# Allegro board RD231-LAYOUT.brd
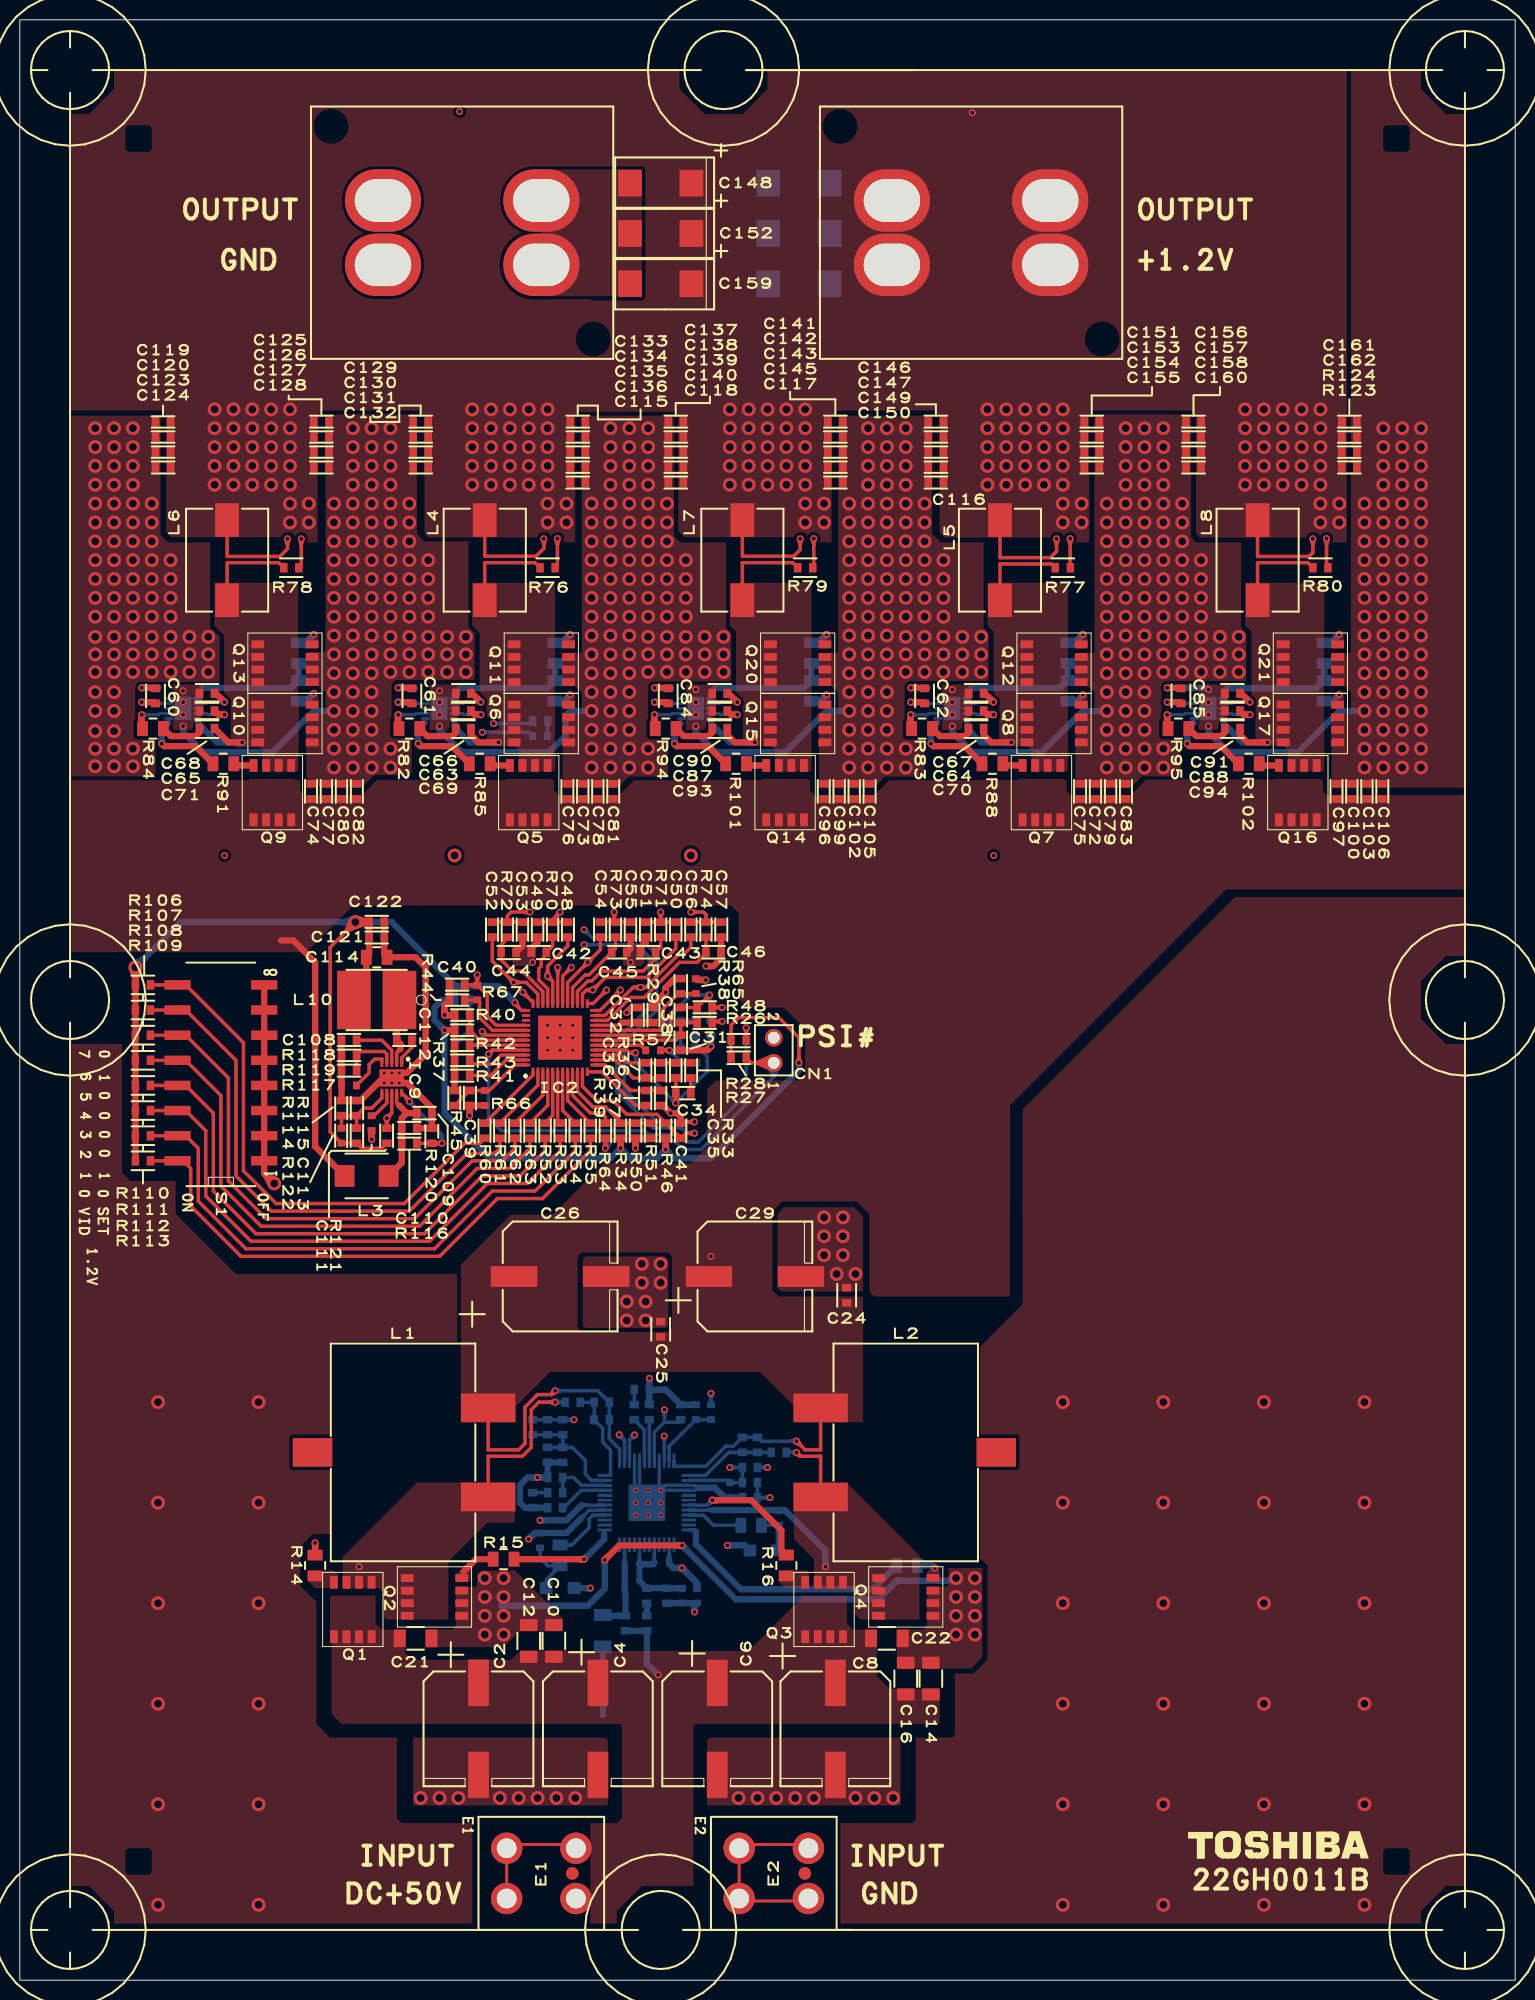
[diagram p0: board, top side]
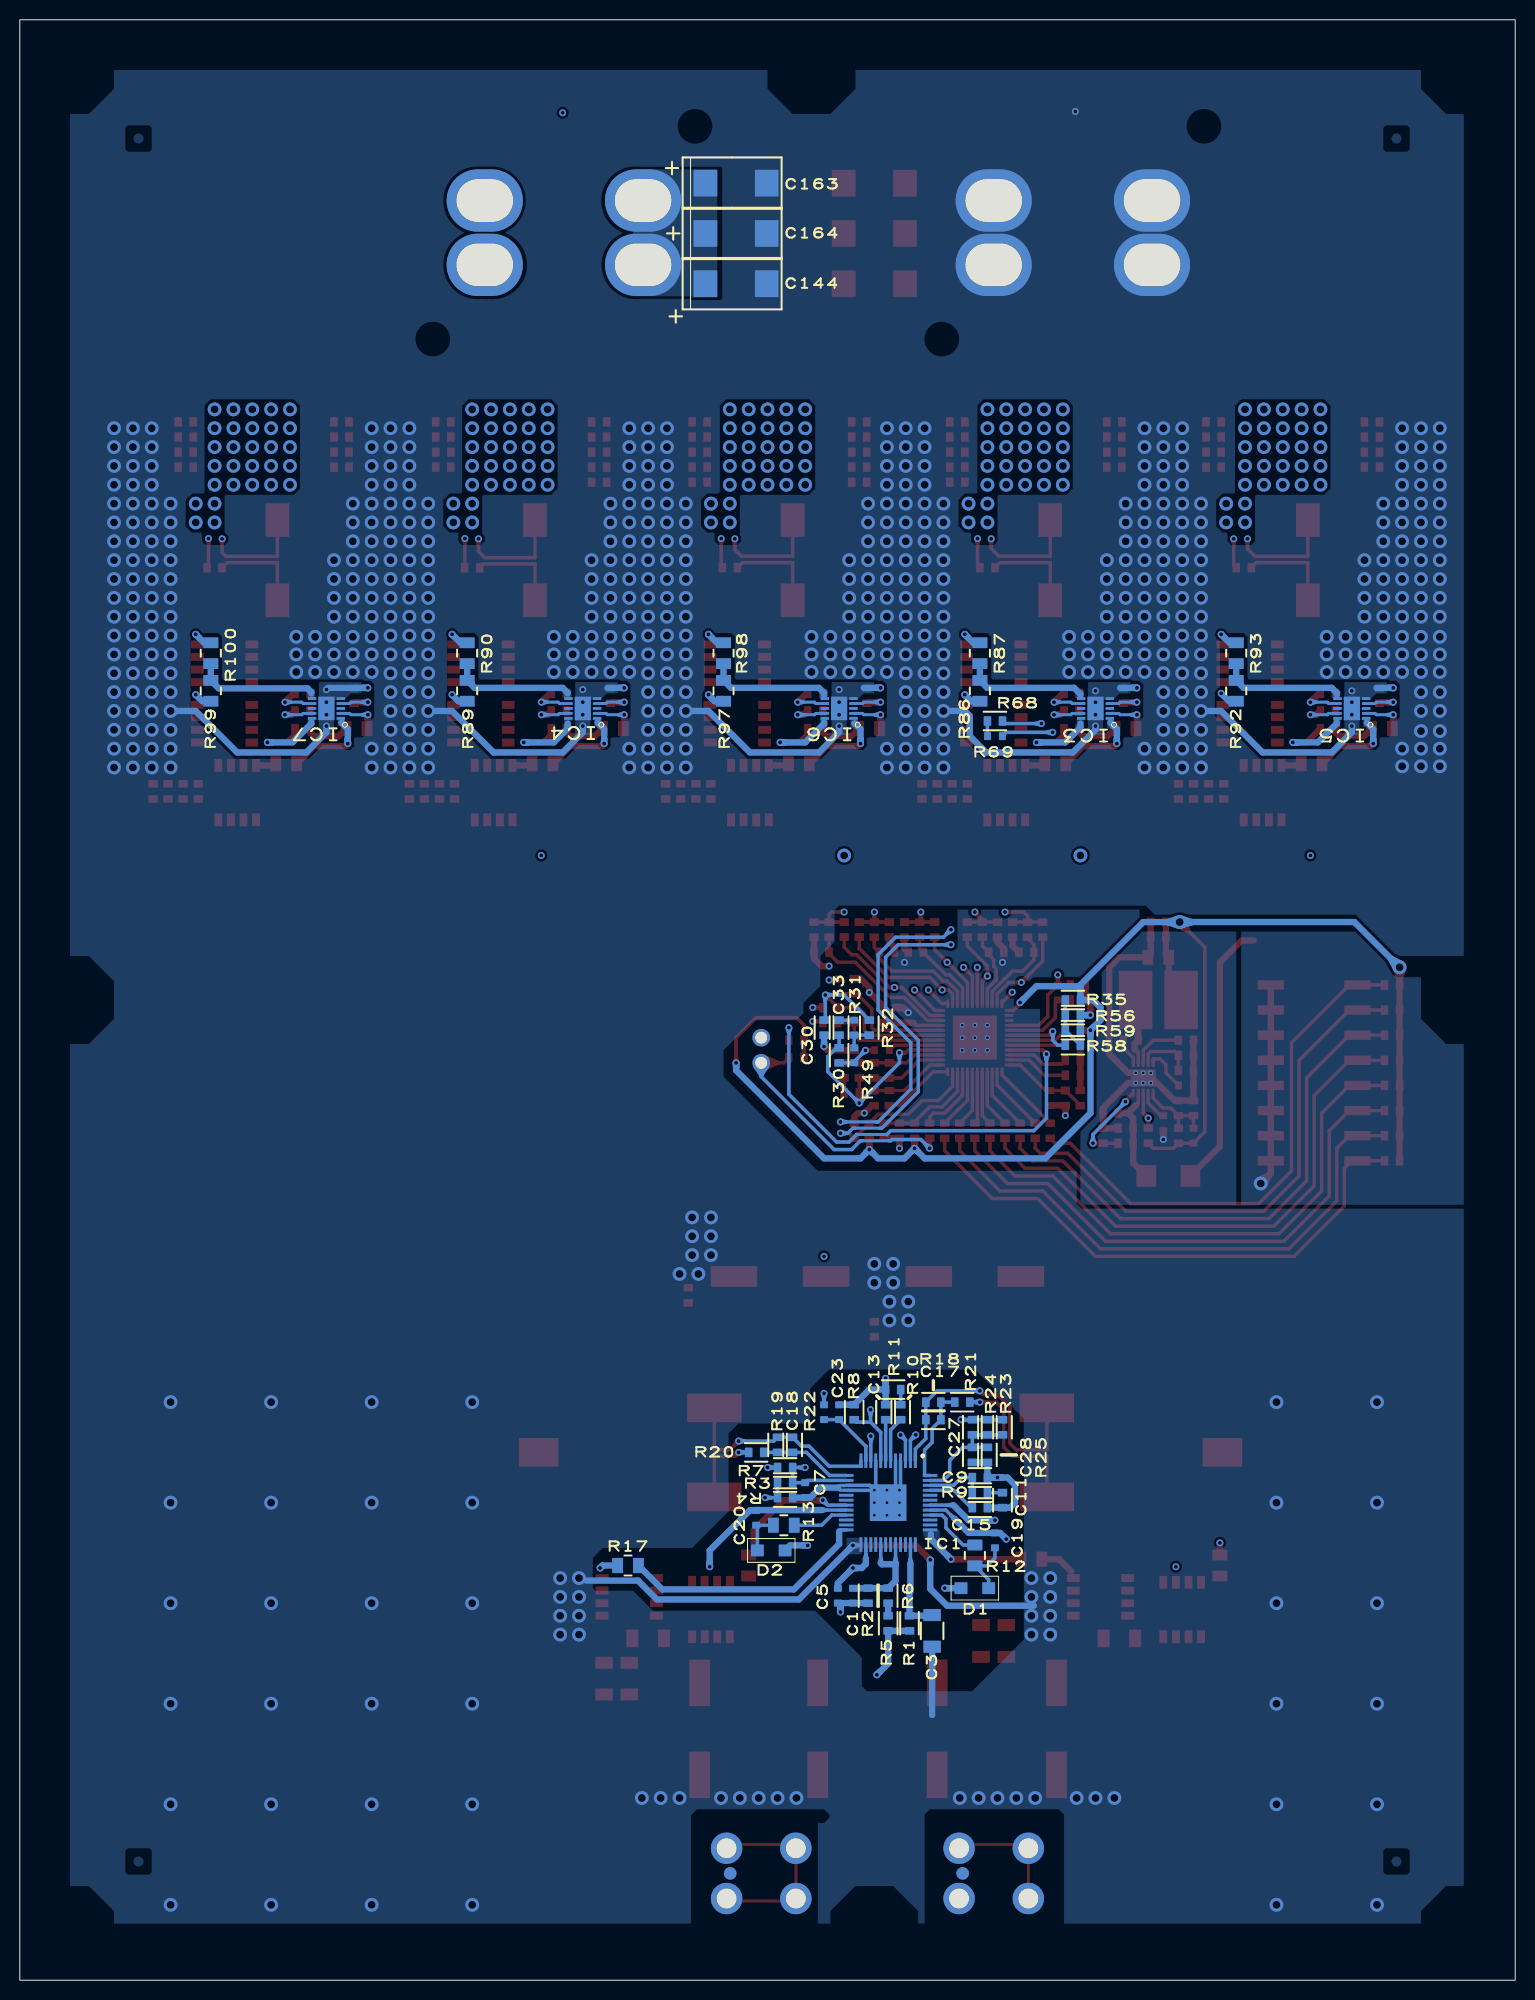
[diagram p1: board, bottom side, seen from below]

Outline 151.13 x 198.12 mm; copper layers: TOP, CONDUCTIVE2, CONDUCTIVE3, CONDUCTIVE4, CONDUCTIVE5, BOTTOM. Coordinates in mm from the lower left corner of the outline.
Outline path: rectangle 0,0 151.13,198.12

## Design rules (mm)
constraint set DEFAULT: 

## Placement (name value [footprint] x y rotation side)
C1  -  [KC00080ATP_P1]  66.93 38.86 270 bottom
C2  -  [DC845R]  46.35 25.4 90 top
C3  -  [DC820R_P2]  58.93 35.31 270 bottom
C4  -  [DC845R]  58.42 25.4 90 top
C5  -  [KC00080ATP_P3]  68.45 38.86 270 bottom
C6  -  [DC845R]  70.48 25.4 90 top
C7  -  [KC00080ATP_P1]  71.75 49.53 270 bottom
C8  -  [DC845R]  82.42 25.4 90 top
C9  -  [C8100E_P66]  54.1 50.8 180 bottom
C10  -  [DC820R_P2]  53.98 34.29 270 top
C11  -  [C8100E_P121]  51.82 48.51 270 bottom
C12  -  [DC820R_P2]  51.44 34.29 270 top
C13  -  [C8100E_P122]  63.63 57.4 90 bottom
C14  -  [DC820R_P2]  92.08 30.48 270 top
C15  -  [C8100E_P44]  54.1 47.75 180 bottom
C16  -  [DC820R_P2]  89.53 30.48 270 top
C17  -  [C8100E_P23]  58.8 56.64 0 bottom
C18  -  [C8100E_P23]  73.03 54.1 270 bottom
C19  -  [KC00080ATP_P1]  52.58 44.45 90 bottom
C20  -  [KC00080ATP_P1]  76.71 46.74 90 bottom
C21  -  [DC820R]  40.01 34.54 0 top
C22  -  [DC820R]  87.63 34.54 0 top
C23  -  [KC00080ATP_P1]  68.33 57.4 90 bottom
C24  -  [C24_C8100E_P1]  83.57 69.22 90 top
C25  -  [C25_C8100E_P2]  64.77 65.79 90 top
C26  -  [DC845R]  54.61 71.12 180 top
C27  -  [C8100E_P3]  54.86 55.88 270 bottom
C28  -  [C8100E_P3]  54.86 53.09 270 bottom
C29  -  [DC845R]  74.3 71.12 180 top
C30  -  [C8100E_P5]  69.85 96.27 270 bottom
C31  -  [C8100E_P5]  66.8 94.74 270 top
C32  -  [C32_C8100E_P7]  62.48 97.54 90 top
C33  -  [C8100E_P8]  68.33 96.27 270 bottom
C34  -  [C8100E_P9]  67.06 89.66 0 top
C35  -  [C8100E_P10]  66.29 91.95 90 top
C36  -  [C8100E_P11]  63.25 91.95 270 top
C37  -  [C8100E_P12]  64.77 89.15 270 top
C38  -  [C8100E_P5]  66.8 97.54 90 top
C39  -  [C8100E_P5]  45.47 89.15 270 top
C40  -  [C8100E_P12]  44.2 100.58 180 top
C41  -  [C8100E_P8]  66.8 85.85 90 top
C42  -  [C8100E_P17]  52.45 103.89 180 top
C43  -  [C8100E_P17]  63.5 103.89 180 top
C44  -  [C8100E_P17]  49.4 103.89 0 top
C45  -  [C8100E_P17]  60.58 103.89 0 top
C46  -  [C8100E_P17]  70.1 103.89 0 top
C48  -  [C8100E_P22]  55.37 106.17 90 top
C49  -  [C8100E_P23]  52.32 106.17 270 top
C50  -  [C8100E_P22]  66.29 106.17 90 top
C51  -  [C8100E_P23]  63.25 106.17 270 top
C52  -  [C8100E_P22]  47.75 106.17 90 top
C53  -  [C8100E_P23]  50.8 106.17 270 top
C54  -  [C8100E_P22]  58.67 106.17 90 top
C55  -  [C8100E_P23]  61.72 106.17 270 top
C56  -  [C8100E_P22]  67.82 106.17 90 top
C57  -  [C8100E_P23]  70.87 106.17 270 top
C60  -  [C8100E_P3]  13.72 129.79 90 top
C61  -  [C8100E_P3]  39.62 129.79 90 top
C62  -  [C8100E_P3]  91.44 129.79 90 top
C63  -  [C63_C8100E_P35]  44.83 128.27 180 top
C64  -  [C64_C8100E_P36]  96.65 128.27 180 top
C65  -  [C65_C8100E_P37]  18.92 128.27 180 top
C66  -  [C66_C8100E_P38]  44.83 130.05 180 top
C67  -  [C67_C8100E_P39]  96.65 130.05 180 top
C68  -  [C68_C8100E_P40]  18.92 130.05 180 top
C69  -  [C8100E_P41]  44.83 126.49 0 top
C70  -  [C8100E_P41]  96.65 126.49 0 top
C71  -  [C8100E_P41]  18.92 126.49 0 top
C72  -  [C8100E_P44]  108.71 120.14 90 top
C73  -  [C8100E_P44]  56.9 120.14 90 top
C74  -  [C8100E_P44]  29.46 120.14 90 top
C75  -  [C8100E_P44]  107.19 120.14 90 top
C76  -  [C8100E_P44]  55.37 120.14 90 top
C77  -  [C8100E_P44]  30.99 120.14 90 top
C78  -  [C78_C8100E_P49]  58.42 120.14 90 top
C79  -  [C79_C8100E_P50]  110.24 120.14 90 top
C80  -  [C80_C8100E_P51]  32.51 120.14 90 top
C81  -  [C81_C8100E_P52]  59.94 120.14 90 top
C82  -  [C82_C8100E_P53]  34.04 120.14 90 top
C83  -  [C83_C8100E_P54]  111.76 120.14 90 top
C84  -  [C8100E_P3]  65.53 129.79 90 top
C85  -  [C8100E_P3]  117.35 129.79 90 top
C87  -  [C87_C8100E_P57]  70.74 128.27 180 top
C88  -  [C88_C8100E_P58]  122.56 128.27 180 top
C90  -  [C90_C8100E_P59]  70.74 130.05 180 top
C91  -  [C91_C8100E_P60]  122.56 130.05 180 top
C93  -  [C8100E_P41]  70.74 126.49 0 top
C94  -  [C8100E_P41]  122.56 126.49 0 top
C96  -  [C8100E_P44]  81.28 120.14 90 top
C97  -  [C8100E_P44]  133.1 120.14 90 top
C99  -  [C8100E_P44]  82.8 120.14 90 top
C100  -  [C8100E_P44]  134.62 120.14 90 top
C102  -  [C102_C8100E_P68]  84.33 120.14 90 top
C103  -  [C103_C8100E_P69]  136.14 120.14 90 top
C105  -  [C105_C8100E_P70]  85.85 120.14 90 top
C106  -  [C106_C8100E_P71]  137.67 120.14 90 top
C108  -  [C108_C8100E_P72]  33.27 95 0 top
C109  -  [C109_C8100E_P73]  40.89 87.63 0 top
C110  -  [C8100E_P74]  39.37 86.11 180 top
C111  -  [KC00080ATP_P7]  35.56 86.61 90 top
C112  -  [C8100E_P74]  38.86 95 0 top
C113  -  [C8100E_P3]  34.04 85.34 270 top
C114  -  [DC810R]  36.07 103.38 0 top
C115  -  [C115_C8100E_P77]  56.39 151.38 180 top
C116  -  [C116_C8100E_P78]  92.58 151.38 0 top
C117  -  [C117_C8100E_P79]  82.42 151.38 180 top
C118  -  [C118_C8100E_P80]  66.29 151.38 0 top
C119  -  [C119_C8100E_P81]  14.48 157.48 0 top
C120  -  [C120_C8100E_P82]  14.48 155.96 0 top
C121  -  [C121_C8100E_P83]  36.07 105.41 0 top
C122  -  [C122_C8100E_P84]  36.07 106.93 180 top
C123  -  [C123_C8100E_P85]  14.48 154.43 0 top
C124  -  [C124_C8100E_P86]  14.48 152.91 0 top
C125  -  [C125_C8100E_P87]  30.48 157.48 180 top
C126  -  [C126_C8100E_P88]  30.48 155.96 180 top
C127  -  [C127_C8100E_P89]  30.48 154.43 180 top
C128  -  [C128_C8100E_P90]  30.48 152.91 180 top
C129  -  [C129_C8100E_P91]  40.51 157.48 0 top
C130  -  [C130_C8100E_P92]  40.51 155.96 0 top
C131  -  [C131_C8100E_P93]  40.51 154.43 0 top
C132  -  [C132_C8100E_P94]  40.51 152.91 0 top
C133  -  [C133_C8100E_P95]  56.39 157.48 180 top
C134  -  [C134_C8100E_P96]  56.39 155.96 180 top
C135  -  [C135_C8100E_P97]  56.39 154.43 180 top
C136  -  [C136_C8100E_P98]  56.39 152.91 180 top
C137  -  [C137_C8100E_P99]  66.29 157.48 0 top
C138  -  [C138_C8100E_P100]  66.29 155.96 0 top
C139  -  [C139_C8100E_P101]  66.29 154.43 0 top
C140  -  [C140_C8100E_P102]  66.29 152.91 0 top
C141  -  [C141_C8100E_P103]  82.42 157.48 180 top
C142  -  [C142_C8100E_P104]  82.42 155.96 180 top
C143  -  [C143_C8100E_P105]  82.42 154.43 180 top
C144  -  [DC847R_P1]  78.74 171.45 0 bottom
C145  -  [C145_C8100E_P106]  82.42 152.91 180 top
C146  -  [C146_C8100E_P107]  92.58 157.48 0 top
C147  -  [C147_C8100E_P108]  92.58 155.96 0 top
C148  -  [DC847R_P1]  64.77 181.61 0 top
C149  -  [C149_C8100E_P109]  92.58 154.43 0 top
C150  -  [C150_C8100E_P110]  92.58 152.91 0 top
C151  -  [C151_C8100E_P111]  108.33 157.48 180 top
C152  -  [DC847R_P1]  64.77 176.53 0 top
C153  -  [C153_C8100E_P112]  108.33 155.96 180 top
C154  -  [C154_C8100E_P113]  108.33 154.43 180 top
C155  -  [C155_C8100E_P114]  108.33 152.91 180 top
C156  -  [C156_C8100E_P115]  118.62 157.48 0 top
C157  -  [C157_C8100E_P116]  118.62 155.96 0 top
C158  -  [C158_C8100E_P117]  118.62 154.43 0 top
C159  -  [DC847R_P1]  64.77 171.45 0 top
C160  -  [C160_C8100E_P118]  118.62 152.91 0 top
C161  -  [C161_C8100E_P119]  134.37 157.48 180 top
C162  -  [C162_C8100E_P120]  134.37 155.96 180 top
C163  -  [DC847R_P1]  78.74 181.61 0 bottom
C164  -  [DC847R_P1]  78.74 176.53 0 bottom
CN1  -  [DPJ028]  76.2 92.71 0 top
D1  -  [S_FLAT_TOSHIBA]  54.61 39.62 180 bottom
D2  -  [S_FLAT_TOSHIBA]  75.18 43.43 0 bottom
E1  -  [T114]  52.7 10.79 90 top
E2  -  [T114]  76.2 10.79 90 top
E7  -  [0_CNS0001_023AI_S0]  104.14 173.35 90 top
E8  -  [0_CNS0001_023AI_S0]  52.7 173.35 90 top
IC1  -  [QFP50P900X900X160_49N]  63.37 48.26 270 bottom
IC2  -  [QFN50P700X700X100_49N]  54.61 95.25 90 top
IC3  -  [SON50P300X300X90_11N]  42.42 128.52 0 bottom
IC4  -  [SON50P300X300X90_11N]  94.23 128.52 0 bottom
IC5  -  [SON50P300X300X90_11N]  16.51 128.52 0 bottom
IC6  -  [SON50P300X300X90_11N]  68.33 128.52 0 bottom
IC7  -  [SON50P300X300X90_11N]  120.14 128.52 0 bottom
IC9  -  [SON50P300X300X85_11N]  37.59 91.19 270 top
L1  -  [0_GAL0003_007AR_S0]  38.73 53.34 0 top
L2  -  [0_GAL0003_007AR_S0]  89.53 53.34 180 top
L3  -  [0_MCP0002_180AR1S0]  35.05 81.28 0 top
L4  -  [T146]  46.99 143.51 90 top
L5  -  [T146]  99.06 143.51 90 top
L6  -  [T146]  20.95 143.51 90 top
L7  -  [T146]  73.03 143.51 90 top
L8  -  [T146]  125.09 143.51 90 top
L10  -  [0_BTM0002_232AR1S0]  36.07 99.06 180 top
Q1  -  [SOP_ADVANCE_TOSHIBA_P10]  33.66 37.47 180 top
Q2  -  [SOP_ADVANCE_TOSHIBA_P11]  41.91 38.73 90 top
Q3  -  [SOP_ADVANCE_TOSHIBA_P10]  81.28 37.47 180 top
Q4  -  [SOP_ADVANCE_TOSHIBA_P11]  89.53 38.73 90 top
Q5  -  [SOP_ADVANCE_TOSHIBA]  51.44 120.02 180 top
Q6  -  [SOP_ADVANCE_TOSHIBA]  52.7 127 90 top
Q7  -  [SOP_ADVANCE_TOSHIBA]  103.25 120.02 180 top
Q8  -  [SOP_ADVANCE_TOSHIBA]  104.52 127 90 top
Q9  -  [SOP_ADVANCE_TOSHIBA]  25.53 120.02 180 top
Q10  -  [SOP_ADVANCE_TOSHIBA]  26.8 127 90 top
Q11  -  [SOP_ADVANCE_TOSHIBA]  52.7 133.1 90 top
Q12  -  [SOP_ADVANCE_TOSHIBA]  104.52 133.1 90 top
Q13  -  [SOP_ADVANCE_TOSHIBA]  26.8 133.1 90 top
Q14  -  [SOP_ADVANCE_TOSHIBA]  77.34 120.02 180 top
Q15  -  [SOP_ADVANCE_TOSHIBA]  78.61 127 90 top
Q16  -  [SOP_ADVANCE_TOSHIBA]  129.16 120.02 180 top
Q17  -  [SOP_ADVANCE_TOSHIBA]  130.43 127 90 top
Q20  -  [SOP_ADVANCE_TOSHIBA]  78.61 133.1 90 top
Q21  -  [SOP_ADVANCE_TOSHIBA]  130.43 133.1 90 top
R1  -  [DR802R_P30]  61.21 36.07 90 bottom
R2  -  [DR802R_P37]  65.41 38.86 90 bottom
R3  -  [DR802R_P1]  73.79 50.29 180 bottom
R4  -  [DR802R_P1]  73.79 48.77 0 bottom
R5  -  [DR802R_P44]  63.37 36.07 270 bottom
R6  -  [DR802R_P44]  63.37 38.86 270 bottom
R7  -  [DR802R_P28]  73.79 51.82 180 bottom
R8  -  [DR802R_P47]  66.8 57.4 270 bottom
R9  -  [DR802R_P48]  54.1 49.28 0 bottom
R10  -  [DR802R_P18]  62.1 57.4 270 bottom
R11  -  [DR802R_P19]  62.87 59.69 180 bottom
R12  -  [DR810R_P4]  54.61 42.93 90 bottom
R13  -  [DR810R_P4]  73.91 45.97 180 bottom
R14  -  [R14_DR810R_P6]  29.84 41.91 90 top
R15  -  [R15_DR810R_P7]  48.9 42.55 0 top
R16  -  [R16_DR810R_P8]  77.47 41.91 90 top
R17  -  [R17_DR810R_P9]  89.66 41.91 180 bottom
R18  -  [DR802R_P20]  58.8 58.42 180 bottom
R19  -  [DR802R_P20]  74.55 54.1 90 bottom
R20  -  [DR802R_P22]  76.71 53.34 180 bottom
R21  -  [DR802R_P22]  55.88 58.42 180 bottom
R22  -  [KC00080ATP_P5]  69.85 57.4 270 bottom
R23  -  [DR802R_P24]  51.82 55.88 90 bottom
R24  -  [DR802R_P25]  53.34 55.88 90 bottom
R25  -  [DR802R_P26]  53.34 53.09 90 bottom
R26  -  [DR802R_P27]  69.22 96.77 180 top
R27  -  [DR802R_P28]  72.64 93.22 180 top
R28  -  [DR802R_P16]  72.64 95 180 top
R29  -  [DR802R_P30]  64.01 97.54 90 top
R30  -  [DR802R_P31]  68.33 93.47 270 bottom
R31  -  [KC00080ATP_P5]  66.8 96.27 270 bottom
R32  -  [DR802R_P32]  65.28 96.27 90 bottom
R33  -  [DR802R_P33]  67.82 91.95 270 top
R34  -  [DR802R_P32]  60.71 85.85 270 top
R35  -  [DR802R_P32]  44.7 99.06 180 bottom
R36  -  [DR802R_P37]  64.77 91.95 90 top
R37  -  [DR802R_P32]  44.7 96.01 0 top
R38  -  [DR802R_P1]  66.8 100.46 270 top
R39  -  [DR802R_P16]  63.25 89.15 270 top
R40  -  [DR802R_P28]  44.7 97.54 0 top
R41  -  [DR802R_P1]  44.7 91.44 180 top
R42  -  [DR802R_P16]  44.7 94.49 180 top
R43  -  [DR802R_P16]  44.7 92.96 180 top
R44  -  [DR802R_P32]  44.2 99.06 180 top
R45  -  [DR802R_P16]  43.94 89.15 90 top
R46  -  [DR802R_P55]  65.28 85.85 270 top
R48  -  [DR802R_P27]  69.22 98.3 180 top
R49  -  [KC00080ATP_P5]  66.8 93.47 270 bottom
R50  -  [DR802R_P57]  62.23 85.85 90 top
R51  -  [DR802R_P55]  63.75 85.85 90 top
R52  -  [DR802R_P59]  53.09 85.85 90 top
R53  -  [DR802R_P59]  54.61 85.85 90 top
R54  -  [DR802R_P59]  56.13 85.85 90 top
R55  -  [DR802R_P59]  57.66 85.85 90 top
R56  -  [DR802R_P63]  44.7 97.54 0 bottom
R57  -  [KC00080ATP_P5]  64.01 93.98 180 top
R58  -  [DR802R_P19]  44.7 94.49 0 bottom
R59  -  [DR802R_P65]  44.7 96.01 0 bottom
R60  -  [DR802R_P59]  46.99 85.85 90 top
R61  -  [DR802R_P59]  48.51 85.85 90 top
R62  -  [DR802R_P59]  50.04 85.85 90 top
R63  -  [DR802R_P59]  51.56 85.85 90 top
R64  -  [DR802R_P59]  59.18 85.85 90 top
R65  -  [KC00080ATP_P5]  68.33 100.46 270 top
R66  -  [KC00080ATP_P5]  46.99 89.15 90 top
R67  -  [KC00080ATP_P5]  46.23 99.82 90 top
R68  -  [DR802R_P71]  52.58 127.25 180 bottom
R69  -  [KC00080ATP]  52.58 125.73 0 bottom
R70  -  [DR802R_P72]  53.85 106.17 270 top
R71  -  [DR802R_P72]  64.77 106.17 270 top
R72  -  [DR802R_P72]  49.28 106.17 270 top
R73  -  [DR802R_P72]  60.2 106.17 270 top
R74  -  [DR802R_P72]  69.34 106.17 270 top
R76  -  [DR802R_P77]  53.34 142.75 0 top
R77  -  [DR802R_P77]  105.41 142.75 0 top
R78  -  [DR802R_P77]  27.43 142.75 0 top
R79  -  [DR802R_P77]  79.38 142.75 0 top
R80  -  [DR802R_P77]  131.44 142.75 0 top
R82  -  [DR810R_P4]  39.37 126.49 180 top
R83  -  [DR810R_P4]  91.19 126.49 180 top
R84  -  [DR810R_P4]  13.46 126.49 180 top
R85  -  [R85_DR810R_P13]  46.48 122.94 180 top
R86  -  [R86_DR810R]  54.1 130.3 90 bottom
R87  -  [R87_DR810R_P14]  54.1 134.11 270 bottom
R88  -  [R88_DR810R_P15]  98.3 122.94 180 top
R89  -  [R89_DR810R_P16]  105.92 130.3 90 bottom
R90  -  [R90_DR810R_P17]  105.92 134.11 270 bottom
R91  -  [R91_DR810R_P18]  20.57 122.94 180 top
R92  -  [R92_DR810R_P19]  28.19 130.3 90 bottom
R93  -  [R93_DR810R_P20]  28.19 134.11 270 bottom
R94  -  [DR810R_P4]  65.28 126.49 180 top
R95  -  [DR810R_P4]  117.09 126.49 180 top
R97  -  [R97_DR810R_P23]  80.01 130.3 90 bottom
R98  -  [R98_DR810R_P24]  80.01 134.11 270 bottom
R99  -  [R99_DR810R_P25]  131.83 130.3 90 bottom
R100  -  [R100_DR810R_P1]  131.83 134.11 270 bottom
R101  -  [R101_DR810R_P2]  72.39 122.94 180 top
R102  -  [R102_DR810R_P3]  124.21 122.94 180 top
R106  -  [DR802R_P1]  12.45 100.58 180 top
R107  -  [DR802R_P1]  12.45 98.04 180 top
R108  -  [DR802R_P1]  12.45 95.5 180 top
R109  -  [DR802R_P1]  12.45 92.96 180 top
R110  -  [DR802R_P1]  12.45 90.42 180 top
R111  -  [DR802R_P1]  12.45 87.88 180 top
R112  -  [DR802R_P1]  12.45 85.34 180 top
R113  -  [DR802R_P1]  12.45 82.8 180 top
R114  -  [DR802R_P9]  32.51 88.14 270 top
R115  -  [DR802R_P10]  34.04 88.14 270 top
R116  -  [DR802R_P11]  39.37 84.58 0 top
R117  -  [KC00080ATP_P5]  33.27 90.42 0 top
R118  -  [DR802R_P12]  33.27 93.47 0 top
R119  -  [DR802R_P13]  33.27 91.95 0 top
R120  -  [DR802R_P14]  41.66 85.34 270 top
R121  -  [DR802R_P1]  37.08 85.34 270 top
R122  -  [KC00080ATP_P5]  32.51 85.34 270 top
R123  -  [DR802R_P16]  134.37 152.91 180 top
R124  -  [DR802R_P16]  134.37 154.43 180 top
S1  -  [0_GAL0016_052BR_S0]  20.32 91.69 90 top

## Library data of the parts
C1 C7 C19 C20 C23 = GDM030001005: alternate symbols: (T:KC00080ATP_p1,KC00080ATP_p16,KC00080ATP_p2,KC00080ATP_p4,KC00080ATP_p15;B:KC00080ATP_p1_B,KC00080ATP_p16_B,KC00080ATP_p2_B,KC00080ATP_p4_B,KC00080ATP_p15_B,C20_KC00080ATP_p1,C23_KC00080ATP_p16,C1_KC00080ATP_p2,C7_KC00080ATP_p4,C19_KC00080ATP_p15)
C2 C4 C6 C8 C26 C29 = G36030155199: alternate symbols: (T:DC845R,DC845R_p1,DC845R_p2,DC845R_p3,DC845R_p4,DC845R_p5,C26_DC845R,C29_DC845R_p1,C2_DC845R_p2,C4_DC845R_p3,C6_DC845R_p4,C8_DC845R_p5;B:DC845R_B,DC845R_p1_B,DC845R_p2_B,DC845R_p3_B,DC845R_p4_B,DC845R_p5_B)
C3 C10 C12 C14 C16 = G36030110013: alternate symbols: (T:DC820R_p2,DC820R_p3,DC820R_p4,DC820R_p5,DC820R_p6,C10_DC820R_p3,C12_DC820R_p4,C14_DC820R_p5,C16_DC820R_p6;B:DC820R_p2_B,DC820R_p3_B,DC820R_p4_B,DC820R_p5_B,DC820R_p6_B,C3_DC820R_p2)
C5 = GDM030001182: alternate symbols: (T:KC00080ATP_p3;B:KC00080ATP_p3_B,C5_KC00080ATP_p3)
C9 = G36030011181: alternate symbols: (T:C8100E_p66;B:C8100E_p66_B,C9_C8100E_p66)
C11 = G36030011075: alternate symbols: (T:C8100E_p121;B:C8100E_p121_B,C11_C8100E_p121)
C13 = G36030104111: alternate symbols: (T:C8100E_p122;B:C8100E_p122_B,C13_C8100E_p122)
C15 C72-C77 C96 C97 C99 C100 = G36030011419: alternate symbols: (T:C8100E_p44,C8100E_p45,C8100E,C8100E_p46,C8100E_p47,C8100E_p48,C8100E_p63,C8100E_p64,C8100E_p65,C8100E_p67,C8100E_p123,C72_C8100E_p44,C73_C8100E_p45,C74_C8100E,C75_C8100E_p46,C76_C8100E_p47,C77_C8100E_p48,C96_C8100E_p63,C97_C8100E_p64,C99_C8100E_p65,C100_C8100E_p67;B:C8100E_p44_B,C8100E_p45_B,C8100E_B,C8100E_p46_B,C8100E_p47_B,C8100E_p48_B,C8100E_p63_B,C8100E_p64_B,C8100E_p65_B,C8100E_p67_B,C8100E_p123_B,C15_C8100E_p123)
C17 C18 C49 C51 C53 C55 C57 = G36030104128: alternate symbols: (T:C8100E_p23,C8100E_p25,C8100E_p27,C8100E_p29,C8100E_p31,C8100E_p124,C8100E_p125,C49_C8100E_p23,C51_C8100E_p25,C53_C8100E_p27,C55_C8100E_p29,C57_C8100E_p31;B:C8100E_p23_B,C8100E_p25_B,C8100E_p27_B,C8100E_p29_B,C8100E_p31_B,C8100E_p124_B,C8100E_p125_B,C17_C8100E_p124,C18_C8100E_p125)
C21 C22 = G36030031080: alternate symbols: (T:DC820R,DC820R_p1,C21_DC820R,C22_DC820R_p1;B:DC820R_B,DC820R_p1_B)
C24 C25 C109 C115-C120 C122-C143 C145-C147 C149-C151 C153-C158 C160-C162 = GDM030000053
C27 C28 C60-C62 C84 C85 C113 = G36030011013: alternate symbols: (T:C8100E_p3,C8100E_p4,C8100E_p32,C8100E_p33,C8100E_p34,C8100E_p55,C8100E_p56,C8100E_p76,C60_C8100E_p32,C61_C8100E_p33,C62_C8100E_p34,C84_C8100E_p55,C85_C8100E_p56,C113_C8100E_p76;B:C8100E_p3_B,C8100E_p4_B,C8100E_p32_B,C8100E_p33_B,C8100E_p34_B,C8100E_p55_B,C8100E_p56_B,C8100E_p76_B,C27_C8100E_p3,C28_C8100E_p4)
C30 C31 C38 C39 = G36030011310: alternate symbols: (T:C8100E_p5,C8100E_p6,C8100E_p13,C8100E_p14,C31_C8100E_p6,C38_C8100E_p13,C39_C8100E_p14;B:C8100E_p5_B,C8100E_p6_B,C8100E_p13_B,C8100E_p14_B,C30_C8100E_p5)
C32 C63-C68 C78-C83 C87 C88 C90 C91 C102 C103 C105 C106 C108 C121 = G36030011433
C33 C41 = G36030011297: alternate symbols: (T:C8100E_p8,C8100E_p16,C41_C8100E_p16;B:C8100E_p8_B,C8100E_p16_B,C33_C8100E_p8)
C34 = G36030011037: alternate symbols: (T:C8100E_p9,C34_C8100E_p9;B:C8100E_p9_B)
C35 = G36030011303: alternate symbols: (T:C8100E_p10,C35_C8100E_p10;B:C8100E_p10_B)
C36 = G36030011747: alternate symbols: (T:C8100E_p11,C36_C8100E_p11;B:C8100E_p11_B)
C37 C40 = G36030011044: alternate symbols: (T:C8100E_p12,C8100E_p15,C37_C8100E_p12,C40_C8100E_p15;B:C8100E_p12_B,C8100E_p15_B)
C42-C46 = G36030011488: alternate symbols: (T:C8100E_p17,C8100E_p18,C8100E_p19,C8100E_p20,C8100E_p21,C42_C8100E_p17,C43_C8100E_p18,C44_C8100E_p19,C45_C8100E_p20,C46_C8100E_p21;B:C8100E_p17_B,C8100E_p18_B,C8100E_p19_B,C8100E_p20_B,C8100E_p21_B)
C48 C50 C52 C54 C56 = GDM030000714: alternate symbols: (T:C8100E_p22,C8100E_p24,C8100E_p26,C8100E_p28,C8100E_p30,C48_C8100E_p22,C50_C8100E_p24,C52_C8100E_p26,C54_C8100E_p28,C56_C8100E_p30;B:C8100E_p22_B,C8100E_p24_B,C8100E_p26_B,C8100E_p28_B,C8100E_p30_B)
C69-C71 C93 C94 = G36030104104: alternate symbols: (T:C8100E_p41,C8100E_p42,C8100E_p43,C8100E_p61,C8100E_p62,C69_C8100E_p41,C70_C8100E_p42,C71_C8100E_p43,C93_C8100E_p61,C94_C8100E_p62;B:C8100E_p41_B,C8100E_p42_B,C8100E_p43_B,C8100E_p61_B,C8100E_p62_B)
C110 C112 = G36030104036: alternate symbols: (T:C8100E_p74,C8100E_p75,C110_C8100E_p74,C112_C8100E_p75;B:C8100E_p74_B,C8100E_p75_B)
C111 = GDM030001137: alternate symbols: (T:KC00080ATP_p7,C111_KC00080ATP_p7;B:KC00080ATP_p7_B)
C114 = GDM030000019: alternate symbols: (T:DC810R,C114_DC810R;B:DC810R_B)
C144 C148 C152 C159 C163 C164 = G36030149044: alternate symbols: (T:DC847R_p1,DC847R_p2,DC847R_p3,DC847R,DC847R_p4,DC847R_p5,C148_DC847R_p2,C152_DC847R_p3,C159_DC847R;B:DC847R_p1_B,DC847R_p2_B,DC847R_p3_B,DC847R_B,DC847R_p4_B,DC847R_p5_B,C144_DC847R_p1,C163_DC847R_p4,C164_DC847R_p5)
CN1 = ZS_DPJ028: alternate symbols: (T:DPJ028;B:DPJ028_B)
D1 D2 = CRH01_Toshiba: alternate symbols: (T:S_FLAT_Toshiba;B:S_FLAT_Toshiba_B)
E1 E2 = 5P9L1232P001: alternate symbols: (T:T114;B:T114_B)
E7 E8 = OP-1100: alternate symbols: (T:0_cns0001_023ai_s0;B:0_cns0001_023ai_s0_B)
IC1 = LTC7810ILXEPBF: alternate symbols: (T:QFP50P900X900X160_49N;B:QFP50P900X900X160_49N_B,IC1_QFP50P900X900X160_49N)
IC2 = ISL6336DIRZ: alternate symbols: (T:QFN50P700X700X100_49N,IC2_QFN50P700X700X100_49N;B:QFN50P700X700X100_49N_B)
IC3-IC7 = ISL6596IRZ-T: alternate symbols: (T:SON50P300X300X90_11N,SON50P300X300X90_11N_p1,SON50P300X300X90_11N_p2,SON50P300X300X90_11N_p3,SON50P300X300X90_11N_p4;B:SON50P300X300X90_11N_B,SON50P300X300X90_11N_p1_B,SON50P300X300X90_11N_p2_B,SON50P300X300X90_11N_p3_B,SON50P300X300X90_11N_p4_B,IC3_SON50P300X300X90_11N,IC4_SON50P300X300X90_11N_p1,IC5_SON50P300X300X90_11N_p2,IC6_SON50P300X300X90_11N_p3,IC7_SON50P300X300X90_11N_p4)
IC9 = LT8609AHDDM-5TRPBF: alternate symbols: (T:SON50P300X300X85_11N,IC9_SON50P300X300X85_11N;B:SON50P300X300X85_11N_B)
L1 L2 = 7443630140: alternate symbols: (T:0_gal0003_007ar_s0,0_gal0003_007ar_s0_p1,L1_0_gal0003_007ar_s0,L2_0_gal0003_007ar_s0_p1;B:0_gal0003_007ar_s0_B,0_gal0003_007ar_s0_p1_B)
L3 = 74437324100: alternate symbols: (T:0_mcp0002_180ar1s0,L3_0_mcp0002_180ar1s0;B:0_mcp0002_180ar1s0_B)
L4-L8 = 7443082022: alternate symbols: (T:T146,T146_p1,T146_p2,T146_p3,T146_p4,L4_T146,L5_T146_p1,L6_T146_p2,L7_T146_p3,L8_T146_p4;B:T146_B,T146_p1_B,T146_p2_B,T146_p3_B,T146_p4_B)
L10 = 744774022: alternate symbols: (T:0_btm0002_232ar1s0,L10_0_btm0002_232ar1s0;B:0_btm0002_232ar1s0_B)
Q1 Q3 = TPH1400ANH_Toshiba: alternate symbols: (T:SOP_Advance_Toshiba_p10;B:SOP_Advance_Toshiba_p10_B)
Q2 Q4 = TPH5R60APL_Toshiba: alternate symbols: (T:SOP_Advance_Toshiba_p11;B:SOP_Advance_Toshiba_p11_B)
Q5-Q17 Q20 Q21 = TPH8R903NL_Toshiba: alternate symbols: (T:SOP_Advance_Toshiba;B:SOP_Advance_Toshiba_B)
R1 R29 = G36010141013: alternate symbols: (T:DR802R_p30,DR802R_p35,R29_DR802R_p30;B:DR802R_p30_B,DR802R_p35_B,R1_DR802R_p35)
R2 R36 = G36010027188: alternate symbols: (T:DR802R_p37,DR802R_p38,R36_DR802R_p37;B:DR802R_p37_B,DR802R_p38_B,R2_DR802R_p38)
R3 R4 R38 R41 R106-R113 R121 = G36010027034: alternate symbols: (T:DR802R_p1,DR802R_p2,DR802R_p3,DR802R_p4,DR802R_p5,DR802R_p6,DR802R_p7,DR802R_p8,DR802R_p15,DR802R_p40,DR802R_p41,DR802R_p42,DR802R_p50,R106_DR802R_p1,R107_DR802R_p2,R108_DR802R_p3,R109_DR802R_p4,R110_DR802R_p5,R111_DR802R_p6,R112_DR802R_p7,R113_DR802R_p8,R121_DR802R_p15,R38_DR802R_p41,R41_DR802R_p50;B:DR802R_p1_B,DR802R_p2_B,DR802R_p3_B,DR802R_p4_B,DR802R_p5_B,DR802R_p6_B,DR802R_p7_B,DR802R_p8_B,DR802R_p15_B,DR802R_p40_B,DR802R_p41_B,DR802R_p42_B,DR802R_p50_B,R3_DR802R_p40,R4_DR802R_p42)
R5 R6 = G36010027300: alternate symbols: (T:DR802R_p44,DR802R_p45;B:DR802R_p44_B,DR802R_p45_B,R5_DR802R_p44,R6_DR802R_p45)
R7 R27 R40 = G36010027133: alternate symbols: (T:DR802R_p28,DR802R_p46,DR802R_p49,R27_DR802R_p28,R40_DR802R_p49;B:DR802R_p28_B,DR802R_p46_B,DR802R_p49_B,R7_DR802R_p46)
R8 = G36010027089: alternate symbols: (T:DR802R_p47;B:DR802R_p47_B,R8_DR802R_p47)
R9 = G36010027041: alternate symbols: (T:DR802R_p48;B:DR802R_p48_B,R9_DR802R_p48)
R10 = G36010129578: alternate symbols: (T:DR802R_p18;B:DR802R_p18_B,R10_DR802R_p18)
R11 R58 = G36010129356: alternate symbols: (T:DR802R_p19,DR802R_p64;B:DR802R_p19_B,DR802R_p64_B,R11_DR802R_p19,R58_DR802R_p64)
R12 R13 R82-R84 R94 R95 = G36010106012: alternate symbols: (T:DR810R_p4,DR810R_p5,DR810R_p10,DR810R_p11,DR810R_p12,DR810R_p21,DR810R_p22,R82_DR810R_p10,R83_DR810R_p11,R84_DR810R_p12,R94_DR810R_p21,R95_DR810R_p22;B:DR810R_p4_B,DR810R_p5_B,DR810R_p10_B,DR810R_p11_B,DR810R_p12_B,DR810R_p21_B,DR810R_p22_B,R12_DR810R_p4,R13_DR810R_p5)
R14-R17 R85-R93 R97-R102 = G36010106081
R18 R19 = G36010027058: alternate symbols: (T:DR802R_p20,DR802R_p21;B:DR802R_p20_B,DR802R_p21_B,R18_DR802R_p20,R19_DR802R_p21)
R20 R21 = G5101105R107: alternate symbols: (T:DR802R_p22,DR802R_p23;B:DR802R_p22_B,DR802R_p23_B,R20_DR802R_p22,R21_DR802R_p23)
R22 R31 R49 R57 R65-R67 R117 R122 = K0100346: alternate symbols: (T:KC00080ATP_p5,KC00080ATP_p6,KC00080ATP_p8,KC00080ATP_p9,KC00080ATP_p10,KC00080ATP_p11,KC00080ATP_p12,KC00080ATP_p13,KC00080ATP_p14,R117_KC00080ATP_p5,R122_KC00080ATP_p6,R57_KC00080ATP_p11,R65_KC00080ATP_p12,R66_KC00080ATP_p13,R67_KC00080ATP_p14;B:KC00080ATP_p5_B,KC00080ATP_p6_B,KC00080ATP_p8_B,KC00080ATP_p9_B,KC00080ATP_p10_B,KC00080ATP_p11_B,KC00080ATP_p12_B,KC00080ATP_p13_B,KC00080ATP_p14_B,R22_KC00080ATP_p8,R31_KC00080ATP_p9,R49_KC00080ATP_p10)
R23 = G5101106F106: alternate symbols: (T:DR802R_p24;B:DR802R_p24_B,R23_DR802R_p24)
R24 = G5101109J104: alternate symbols: (T:DR802R_p25;B:DR802R_p25_B,R24_DR802R_p25)
R25 = G36010129493: alternate symbols: (T:DR802R_p26;B:DR802R_p26_B,R25_DR802R_p26)
R26 R48 = G36010104063: alternate symbols: (T:DR802R_p27,DR802R_p56,R26_DR802R_p27,R48_DR802R_p56;B:DR802R_p27_B,DR802R_p56_B)
R28 R39 R42 R43 R45 R123 R124 = G36010027324: alternate symbols: (T:DR802R_p16,DR802R_p17,DR802R_p29,DR802R_p43,DR802R_p51,DR802R_p52,DR802R_p54,R123_DR802R_p16,R124_DR802R_p17,R28_DR802R_p29,R39_DR802R_p43,R42_DR802R_p51,R43_DR802R_p52,R45_DR802R_p54;B:DR802R_p16_B,DR802R_p17_B,DR802R_p29_B,DR802R_p43_B,DR802R_p51_B,DR802R_p52_B,DR802R_p54_B)
R30 = G36010104339: alternate symbols: (T:DR802R_p31;B:DR802R_p31_B,R30_DR802R_p31)
R32 R34 R35 R37 R44 = G36010129400: alternate symbols: (T:DR802R_p32,DR802R_p34,DR802R_p36,DR802R_p39,DR802R_p53,R34_DR802R_p34,R37_DR802R_p39,R44_DR802R_p53;B:DR802R_p32_B,DR802R_p34_B,DR802R_p36_B,DR802R_p39_B,DR802R_p53_B,R32_DR802R_p32,R35_DR802R_p36)
R33 = G36010104353: alternate symbols: (T:DR802R_p33,R33_DR802R_p33;B:DR802R_p33_B)
R46 R51 = G5101106E109: alternate symbols: (T:DR802R_p55,DR802R_p58,R46_DR802R_p55,R51_DR802R_p58;B:DR802R_p55_B,DR802R_p58_B)
R50 = G36010129639: alternate symbols: (T:DR802R_p57,R50_DR802R_p57;B:DR802R_p57_B)
R52-R55 R60-R64 = G36010104087: alternate symbols: (T:DR802R_p59,DR802R_p60,DR802R_p61,DR802R_p62,DR802R_p66,DR802R_p67,DR802R_p68,DR802R_p69,DR802R_p70,R52_DR802R_p59,R53_DR802R_p60,R54_DR802R_p61,R55_DR802R_p62,R60_DR802R_p66,R61_DR802R_p67,R62_DR802R_p68,R63_DR802R_p69,R64_DR802R_p70;B:DR802R_p59_B,DR802R_p60_B,DR802R_p61_B,DR802R_p62_B,DR802R_p66_B,DR802R_p67_B,DR802R_p68_B,DR802R_p69_B,DR802R_p70_B)
R56 = G36010014355: alternate symbols: (T:DR802R_p63;B:DR802R_p63_B,R56_DR802R_p63)
R59 = G36010129714: alternate symbols: (T:DR802R_p65;B:DR802R_p65_B,R59_DR802R_p65)
R68 = G36010027164: alternate symbols: (T:DR802R_p71;B:DR802R_p71_B,R68_DR802R_p71)
R69 = K0900027: alternate symbols: (T:KC00080ATP;B:KC00080ATP_B,R69_KC00080ATP)
R70-R74 = G5101104N107: alternate symbols: (T:DR802R_p72,DR802R_p73,DR802R_p74,DR802R_p75,DR802R_p76,R70_DR802R_p72,R71_DR802R_p73,R72_DR802R_p74,R73_DR802R_p75,R74_DR802R_p76;B:DR802R_p72_B,DR802R_p73_B,DR802R_p74_B,DR802R_p75_B,DR802R_p76_B)
R76-R80 = G36010104094: alternate symbols: (T:DR802R_p77,DR802R_p78,DR802R_p79,DR802R,DR802R_p80,R76_DR802R_p77,R77_DR802R_p78,R78_DR802R_p79,R79_DR802R,R80_DR802R_p80;B:DR802R_p77_B,DR802R_p78_B,DR802R_p79_B,DR802R_B,DR802R_p80_B)
R114 = G36010104216: alternate symbols: (T:DR802R_p9,R114_DR802R_p9;B:DR802R_p9_B)
R115 = G36010103110: alternate symbols: (T:DR802R_p10,R115_DR802R_p10;B:DR802R_p10_B)
R116 = G36010027171: alternate symbols: (T:DR802R_p11,R116_DR802R_p11;B:DR802R_p11_B)
R118 = G36010129592: alternate symbols: (T:DR802R_p12,R118_DR802R_p12;B:DR802R_p12_B)
R119 = G36010014676: alternate symbols: (T:DR802R_p13,R119_DR802R_p13;B:DR802R_p13_B)
R120 = G36010104254: alternate symbols: (T:DR802R_p14,R120_DR802R_p14;B:DR802R_p14_B)
S1 = 219-8LPST: alternate symbols: (T:0_gal0016_052br_s0,S1_0_gal0016_052br_s0;B:0_gal0016_052br_s0_B)

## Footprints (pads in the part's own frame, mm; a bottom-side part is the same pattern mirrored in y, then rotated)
0_BTM0002_232AR1S0
  custom 0.85x0.85 smd: 1(-2.3,0) 2(2.3,0)
0_CNS0001_023AI_S0
  oval 6.3x7.7 hole 4.3x5.7: 1(0,0) 2(6.5,0) 3(6.5,16) 4(0,16)
  round 0.01 hole 2.5: 5(-7.5,-5.25) 6(14,21.25)
0_GAL0003_007AR_S0
  custom 0.725x0.725 smd: 1(8.6,-4.5) 2(8.6,4.5) 3(-9.15,0)
0_GAL0016_052BR_S0
  custom 0.237x0.237 smd: 1(-8.89,-4.38) 2(-6.35,-4.38) 3(-3.81,-4.38) 4(-1.27,-4.38) 5(1.27,-4.38) 6(3.81,-4.38) 7(6.35,-4.38) 8(8.89,-4.38) 9(8.89,4.38) 10(6.35,4.38) 11(3.81,4.38) 12(1.27,4.38) 13(-1.27,4.38) 14(-3.81,4.38) 15(-6.35,4.38) 16(-8.89,4.38)
0_MCP0002_180AR1S0
  custom 0.5x0.5 smd: 1(-2.225,0) 2(2.225,0)
C24_C8100E_P1
  custom 0.194x0.194 smd: 1(-0.762,0) 2(0.762,0)
C25_C8100E_P2
  custom 0.194x0.194 smd: 1(-0.762,0) 2(0.762,0)
C32_C8100E_P7
  custom 0.194x0.194 smd: 1(-0.762,0) 2(0.762,0)
C63_C8100E_P35
  custom 0.194x0.194 smd: 1(-0.762,0) 2(0.762,0)
C64_C8100E_P36
  custom 0.194x0.194 smd: 1(-0.762,0) 2(0.762,0)
C65_C8100E_P37
  custom 0.194x0.194 smd: 1(-0.762,0) 2(0.762,0)
C66_C8100E_P38
  custom 0.194x0.194 smd: 1(-0.762,0) 2(0.762,0)
C67_C8100E_P39
  custom 0.194x0.194 smd: 1(-0.762,0) 2(0.762,0)
C68_C8100E_P40
  custom 0.194x0.194 smd: 1(-0.762,0) 2(0.762,0)
C78_C8100E_P49
  custom 0.194x0.194 smd: 1(-0.762,0) 2(0.762,0)
C79_C8100E_P50
  custom 0.194x0.194 smd: 1(-0.762,0) 2(0.762,0)
C80_C8100E_P51
  custom 0.194x0.194 smd: 1(-0.762,0) 2(0.762,0)
C81_C8100E_P52
  custom 0.194x0.194 smd: 1(-0.762,0) 2(0.762,0)
C82_C8100E_P53
  custom 0.194x0.194 smd: 1(-0.762,0) 2(0.762,0)
C83_C8100E_P54
  custom 0.194x0.194 smd: 1(-0.762,0) 2(0.762,0)
C87_C8100E_P57
  custom 0.194x0.194 smd: 1(-0.762,0) 2(0.762,0)
C88_C8100E_P58
  custom 0.194x0.194 smd: 1(-0.762,0) 2(0.762,0)
C90_C8100E_P59
  custom 0.194x0.194 smd: 1(-0.762,0) 2(0.762,0)
C91_C8100E_P60
  custom 0.194x0.194 smd: 1(-0.762,0) 2(0.762,0)
C102_C8100E_P68
  custom 0.194x0.194 smd: 1(-0.762,0) 2(0.762,0)
C103_C8100E_P69
  custom 0.194x0.194 smd: 1(-0.762,0) 2(0.762,0)
C105_C8100E_P70
  custom 0.194x0.194 smd: 1(-0.762,0) 2(0.762,0)
C106_C8100E_P71
  custom 0.194x0.194 smd: 1(-0.762,0) 2(0.762,0)
C108_C8100E_P72
  custom 0.194x0.194 smd: 1(-0.762,0) 2(0.762,0)
C109_C8100E_P73
  custom 0.194x0.194 smd: 1(-0.762,0) 2(0.762,0)
C115_C8100E_P77
  custom 0.194x0.194 smd: 1(-0.762,0) 2(0.762,0)
C116_C8100E_P78
  custom 0.194x0.194 smd: 1(-0.762,0) 2(0.762,0)
C117_C8100E_P79
  custom 0.194x0.194 smd: 1(-0.762,0) 2(0.762,0)
C118_C8100E_P80
  custom 0.194x0.194 smd: 1(-0.762,0) 2(0.762,0)
C119_C8100E_P81
  custom 0.194x0.194 smd: 1(-0.762,0) 2(0.762,0)
C120_C8100E_P82
  custom 0.194x0.194 smd: 1(-0.762,0) 2(0.762,0)
C121_C8100E_P83
  custom 0.194x0.194 smd: 1(-0.762,0) 2(0.762,0)
C122_C8100E_P84
  custom 0.194x0.194 smd: 1(-0.762,0) 2(0.762,0)
C123_C8100E_P85
  custom 0.194x0.194 smd: 1(-0.762,0) 2(0.762,0)
C124_C8100E_P86
  custom 0.194x0.194 smd: 1(-0.762,0) 2(0.762,0)
C125_C8100E_P87
  custom 0.194x0.194 smd: 1(-0.762,0) 2(0.762,0)
C126_C8100E_P88
  custom 0.194x0.194 smd: 1(-0.762,0) 2(0.762,0)
C127_C8100E_P89
  custom 0.194x0.194 smd: 1(-0.762,0) 2(0.762,0)
C128_C8100E_P90
  custom 0.194x0.194 smd: 1(-0.762,0) 2(0.762,0)
C129_C8100E_P91
  custom 0.194x0.194 smd: 1(-0.762,0) 2(0.762,0)
C130_C8100E_P92
  custom 0.194x0.194 smd: 1(-0.762,0) 2(0.762,0)
C131_C8100E_P93
  custom 0.194x0.194 smd: 1(-0.762,0) 2(0.762,0)
C132_C8100E_P94
  custom 0.194x0.194 smd: 1(-0.762,0) 2(0.762,0)
C133_C8100E_P95
  custom 0.194x0.194 smd: 1(-0.762,0) 2(0.762,0)
C134_C8100E_P96
  custom 0.194x0.194 smd: 1(-0.762,0) 2(0.762,0)
C135_C8100E_P97
  custom 0.194x0.194 smd: 1(-0.762,0) 2(0.762,0)
C136_C8100E_P98
  custom 0.194x0.194 smd: 1(-0.762,0) 2(0.762,0)
C137_C8100E_P99
  custom 0.194x0.194 smd: 1(-0.762,0) 2(0.762,0)
C138_C8100E_P100
  custom 0.194x0.194 smd: 1(-0.762,0) 2(0.762,0)
C139_C8100E_P101
  custom 0.194x0.194 smd: 1(-0.762,0) 2(0.762,0)
C140_C8100E_P102
  custom 0.194x0.194 smd: 1(-0.762,0) 2(0.762,0)
C141_C8100E_P103
  custom 0.194x0.194 smd: 1(-0.762,0) 2(0.762,0)
C142_C8100E_P104
  custom 0.194x0.194 smd: 1(-0.762,0) 2(0.762,0)
C143_C8100E_P105
  custom 0.194x0.194 smd: 1(-0.762,0) 2(0.762,0)
C145_C8100E_P106
  custom 0.194x0.194 smd: 1(-0.762,0) 2(0.762,0)
C146_C8100E_P107
  custom 0.194x0.194 smd: 1(-0.762,0) 2(0.762,0)
C147_C8100E_P108
  custom 0.194x0.194 smd: 1(-0.762,0) 2(0.762,0)
C149_C8100E_P109
  custom 0.194x0.194 smd: 1(-0.762,0) 2(0.762,0)
C150_C8100E_P110
  custom 0.194x0.194 smd: 1(-0.762,0) 2(0.762,0)
C151_C8100E_P111
  custom 0.194x0.194 smd: 1(-0.762,0) 2(0.762,0)
C153_C8100E_P112
  custom 0.194x0.194 smd: 1(-0.762,0) 2(0.762,0)
C154_C8100E_P113
  custom 0.194x0.194 smd: 1(-0.762,0) 2(0.762,0)
C155_C8100E_P114
  custom 0.194x0.194 smd: 1(-0.762,0) 2(0.762,0)
C156_C8100E_P115
  custom 0.194x0.194 smd: 1(-0.762,0) 2(0.762,0)
C157_C8100E_P116
  custom 0.194x0.194 smd: 1(-0.762,0) 2(0.762,0)
C158_C8100E_P117
  custom 0.194x0.194 smd: 1(-0.762,0) 2(0.762,0)
C160_C8100E_P118
  custom 0.194x0.194 smd: 1(-0.762,0) 2(0.762,0)
C161_C8100E_P119
  custom 0.194x0.194 smd: 1(-0.762,0) 2(0.762,0)
C162_C8100E_P120
  custom 0.194x0.194 smd: 1(-0.762,0) 2(0.762,0)
C8100E_P3
  custom 0.194x0.194 smd: 1(-0.762,0) 2(0.762,0)
C8100E_P5
  custom 0.194x0.194 smd: 1(-0.762,0) 2(0.762,0)
C8100E_P8
  custom 0.194x0.194 smd: 1(-0.762,0) 2(0.762,0)
C8100E_P9
  custom 0.194x0.194 smd: 1(-0.762,0) 2(0.762,0)
C8100E_P10
  custom 0.194x0.194 smd: 1(-0.762,0) 2(0.762,0)
C8100E_P11
  custom 0.194x0.194 smd: 1(-0.762,0) 2(0.762,0)
C8100E_P12
  custom 0.194x0.194 smd: 1(-0.762,0) 2(0.762,0)
C8100E_P17
  custom 0.194x0.194 smd: 1(-0.762,0) 2(0.762,0)
C8100E_P22
  custom 0.194x0.194 smd: 1(-0.762,0) 2(0.762,0)
C8100E_P23
  custom 0.194x0.194 smd: 1(-0.762,0) 2(0.762,0)
C8100E_P41
  custom 0.194x0.194 smd: 1(-0.762,0) 2(0.762,0)
C8100E_P44
  custom 0.194x0.194 smd: 1(-0.762,0) 2(0.762,0)
C8100E_P66
  custom 0.194x0.194 smd: 1(-0.762,0) 2(0.762,0)
C8100E_P74
  custom 0.194x0.194 smd: 1(-0.762,0) 2(0.762,0)
C8100E_P121
  custom 0.194x0.194 smd: 1(-0.762,0) 2(0.762,0)
C8100E_P122
  custom 0.194x0.194 smd: 1(-0.762,0) 2(0.762,0)
DC810R
  custom 0.273x0.273 smd: 1(1.054,0) 2(-1.054,0)
DC820R
  custom 0.305x0.305 smd: 1(-1.6,0) 2(1.6,0)
DC820R_P2
  custom 0.305x0.305 smd: 1(-1.6,0) 2(1.6,0)
DC845R
  custom 0.525x0.525 smd: 1(-4.65,0) 2(4.65,0)
DC847R_P1
  custom 0.6x0.6 smd: 1(-3.1,0) 2(3.1,0)
DPJ028
  round 1.778 hole 1.2: 1(0,0) 2(0,2.54)
DR802R_P1
  custom 0.191x0.191 smd: 1(-0.762,0) 2(0.762,0)
DR802R_P9
  custom 0.191x0.191 smd: 1(-0.762,0) 2(0.762,0)
DR802R_P10
  custom 0.191x0.191 smd: 1(-0.762,0) 2(0.762,0)
DR802R_P11
  custom 0.191x0.191 smd: 1(-0.762,0) 2(0.762,0)
DR802R_P12
  custom 0.191x0.191 smd: 1(-0.762,0) 2(0.762,0)
DR802R_P13
  custom 0.191x0.191 smd: 1(-0.762,0) 2(0.762,0)
DR802R_P14
  custom 0.191x0.191 smd: 1(-0.762,0) 2(0.762,0)
DR802R_P16
  custom 0.191x0.191 smd: 1(-0.762,0) 2(0.762,0)
DR802R_P18
  custom 0.191x0.191 smd: 1(-0.762,0) 2(0.762,0)
DR802R_P19
  custom 0.191x0.191 smd: 1(-0.762,0) 2(0.762,0)
DR802R_P20
  custom 0.191x0.191 smd: 1(-0.762,0) 2(0.762,0)
DR802R_P22
  custom 0.191x0.191 smd: 1(-0.762,0) 2(0.762,0)
DR802R_P24
  custom 0.191x0.191 smd: 1(-0.762,0) 2(0.762,0)
DR802R_P25
  custom 0.191x0.191 smd: 1(-0.762,0) 2(0.762,0)
DR802R_P26
  custom 0.191x0.191 smd: 1(-0.762,0) 2(0.762,0)
DR802R_P27
  custom 0.191x0.191 smd: 1(-0.762,0) 2(0.762,0)
DR802R_P28
  custom 0.191x0.191 smd: 1(-0.762,0) 2(0.762,0)
DR802R_P30
  custom 0.191x0.191 smd: 1(-0.762,0) 2(0.762,0)
DR802R_P31
  custom 0.191x0.191 smd: 1(-0.762,0) 2(0.762,0)
DR802R_P32
  custom 0.191x0.191 smd: 1(-0.762,0) 2(0.762,0)
DR802R_P33
  custom 0.191x0.191 smd: 1(-0.762,0) 2(0.762,0)
DR802R_P37
  custom 0.191x0.191 smd: 1(-0.762,0) 2(0.762,0)
DR802R_P44
  custom 0.191x0.191 smd: 1(-0.762,0) 2(0.762,0)
DR802R_P47
  custom 0.191x0.191 smd: 1(-0.762,0) 2(0.762,0)
DR802R_P48
  custom 0.191x0.191 smd: 1(-0.762,0) 2(0.762,0)
DR802R_P55
  custom 0.191x0.191 smd: 1(-0.762,0) 2(0.762,0)
DR802R_P57
  custom 0.191x0.191 smd: 1(-0.762,0) 2(0.762,0)
DR802R_P59
  custom 0.191x0.191 smd: 1(-0.762,0) 2(0.762,0)
DR802R_P63
  custom 0.191x0.191 smd: 1(-0.762,0) 2(0.762,0)
DR802R_P65
  custom 0.191x0.191 smd: 1(-0.762,0) 2(0.762,0)
DR802R_P71
  custom 0.191x0.191 smd: 1(-0.762,0) 2(0.762,0)
DR802R_P72
  custom 0.191x0.191 smd: 1(-0.762,0) 2(0.762,0)
DR802R_P77
  custom 0.191x0.191 smd: 1(-0.762,0) 2(0.762,0)
DR810R_P4
  custom 0.273x0.273 smd: 1(1.054,0) 2(-1.054,0)
KC00080ATP
  custom 0.175x0.175 smd: 1(-0.75,0) 2(0.75,0)
KC00080ATP_P1
  custom 0.175x0.175 smd: 1(-0.75,0) 2(0.75,0)
KC00080ATP_P3
  custom 0.175x0.175 smd: 1(-0.75,0) 2(0.75,0)
KC00080ATP_P5
  custom 0.175x0.175 smd: 1(-0.75,0) 2(0.75,0)
KC00080ATP_P7
  custom 0.175x0.175 smd: 1(-0.75,0) 2(0.75,0)
QFN50P700X700X100_49N
  custom 0.075x0.075 smd: 1(-3.45,2.75) 2(-3.45,2.25) 3(-3.45,1.75) 4(-3.45,1.25) 5(-3.45,0.75) 6(-3.45,0.25) 7(-3.45,-0.25) 8(-3.45,-0.75) 9(-3.45,-1.25) 10(-3.45,-1.75) 11(-3.45,-2.25) 12(-3.45,-2.75) 13(-2.75,-3.45) 14(-2.25,-3.45) 15(-1.75,-3.45) 16(-1.25,-3.45) 17(-0.75,-3.45) 18(-0.25,-3.45) 19(0.25,-3.45) 20(0.75,-3.45) 21(1.25,-3.45) 22(1.75,-3.45) 23(2.25,-3.45) 24(2.75,-3.45) 25(3.45,-2.75) 26(3.45,-2.25) 27(3.45,-1.75) 28(3.45,-1.25) 29(3.45,-0.75) 30(3.45,-0.25) 31(3.45,0.25) 32(3.45,0.75) 33(3.45,1.25) 34(3.45,1.75) 35(3.45,2.25) 36(3.45,2.75) 37(2.75,3.45) 38(2.25,3.45) 39(1.75,3.45) 40(1.25,3.45) 41(0.75,3.45) 42(0.25,3.45) 43(-0.25,3.45) 44(-0.75,3.45) 45(-1.25,3.45) 46(-1.75,3.45) 47(-2.25,3.45) 48(-2.75,3.45)
  custom 1.113x1.113 smd: 49(0,0)
QFP50P900X900X160_49N
  custom 0.075x0.075 smd: 1(-4.238,2.75) 2(-4.238,2.25) 3(-4.238,1.75) 4(-4.238,1.25) 5(-4.238,0.75) 6(-4.238,0.25) 7(-4.238,-0.25) 8(-4.238,-0.75) 9(-4.238,-1.25) 10(-4.238,-1.75) 11(-4.238,-2.25) 12(-4.238,-2.75) 13(-2.75,-4.238) 14(-2.25,-4.238) 15(-1.75,-4.238) 16(-1.25,-4.238) 17(-0.75,-4.238) 18(-0.25,-4.238) 19(0.25,-4.238) 20(0.75,-4.238) 21(1.25,-4.238) 22(1.75,-4.238) 23(2.25,-4.238) 24(2.75,-4.238) 25(4.238,-2.75) 26(4.238,-2.25) 27(4.238,-1.75) 28(4.238,-1.25) 29(4.238,-0.75) 30(4.238,-0.25) 31(4.238,0.25) 32(4.238,0.75) 33(4.238,1.25) 34(4.238,1.75) 35(4.238,2.25) 36(4.238,2.75) 37(2.75,4.238) 38(2.25,4.238) 39(1.75,4.238) 40(1.25,4.238) 41(0.75,4.238) 42(0.25,4.238) 43(-0.25,4.238) 44(-0.75,4.238) 45(-1.25,4.238) 46(-1.75,4.238) 47(-2.25,4.238) 48(-2.75,4.238)
  custom 0.925x0.925 smd: 49(0,0)
R14_DR810R_P6
  custom 0.273x0.273 smd: 1(1.054,0) 2(-1.054,0)
R15_DR810R_P7
  custom 0.273x0.273 smd: 1(1.054,0) 2(-1.054,0)
R16_DR810R_P8
  custom 0.273x0.273 smd: 1(1.054,0) 2(-1.054,0)
R17_DR810R_P9
  custom 0.273x0.273 smd: 1(1.054,0) 2(-1.054,0)
R85_DR810R_P13
  custom 0.273x0.273 smd: 1(1.054,0) 2(-1.054,0)
R86_DR810R
  custom 0.273x0.273 smd: 1(1.054,0) 2(-1.054,0)
R87_DR810R_P14
  custom 0.273x0.273 smd: 1(1.054,0) 2(-1.054,0)
R88_DR810R_P15
  custom 0.273x0.273 smd: 1(1.054,0) 2(-1.054,0)
R89_DR810R_P16
  custom 0.273x0.273 smd: 1(1.054,0) 2(-1.054,0)
R90_DR810R_P17
  custom 0.273x0.273 smd: 1(1.054,0) 2(-1.054,0)
R91_DR810R_P18
  custom 0.273x0.273 smd: 1(1.054,0) 2(-1.054,0)
R92_DR810R_P19
  custom 0.273x0.273 smd: 1(1.054,0) 2(-1.054,0)
R93_DR810R_P20
  custom 0.273x0.273 smd: 1(1.054,0) 2(-1.054,0)
R97_DR810R_P23
  custom 0.273x0.273 smd: 1(1.054,0) 2(-1.054,0)
R98_DR810R_P24
  custom 0.273x0.273 smd: 1(1.054,0) 2(-1.054,0)
R99_DR810R_P25
  custom 0.273x0.273 smd: 1(1.054,0) 2(-1.054,0)
R100_DR810R_P1
  custom 0.273x0.273 smd: 1(1.054,0) 2(-1.054,0)
R101_DR810R_P2
  custom 0.273x0.273 smd: 1(1.054,0) 2(-1.054,0)
R102_DR810R_P3
  custom 0.273x0.273 smd: 1(1.054,0) 2(-1.054,0)
S_FLAT_TOSHIBA
  custom 0.3x0.3 smd: 1(-1.4,0) 2(1.4,0)
SON50P300X300X85_11N
  custom 0.075x0.075 smd: 1(-1.5,1) 2(-1.5,0.5) 3(-1.5,0) 4(-1.5,-0.5) 5(-1.5,-1) 6(1.5,-1) 7(1.5,-0.5) 8(1.5,0) 9(1.5,0.5) 10(1.5,1)
  custom 0.438x0.438 smd: 11(0,0)
SON50P300X300X90_11N
  custom 0.075x0.075 smd: 1(-1.45,1) 2(-1.45,0.5) 3(-1.45,0) 4(-1.45,-0.5) 5(-1.45,-1) 6(1.45,-1) 7(1.45,-0.5) 8(1.45,0) 9(1.45,0.5) 10(1.45,1)
  custom 0.41x0.41 smd: 11(0,0)
SOP_ADVANCE_TOSHIBA
  custom 0.2x0.2 smd: 1(-1.905,-2.75) 2(-0.635,-2.75) 3(0.635,-2.75) 4(1.905,-2.75) 5(1.905,2.75) 6(0.635,2.75) 7(-0.635,2.75) 8(-1.905,2.75)
SOP_ADVANCE_TOSHIBA_P10
  custom 0.2x0.2 smd: 1(-1.905,-2.75) 2(-0.635,-2.75) 3(0.635,-2.75) 4(1.905,-2.75) 5(1.905,2.75) 6(0.635,2.75) 7(-0.635,2.75) 8(-1.905,2.75)
SOP_ADVANCE_TOSHIBA_P11
  custom 0.2x0.2 smd: 1(-1.905,-2.75) 2(-0.635,-2.75) 3(0.635,-2.75) 4(1.905,-2.75) 5(1.905,2.75) 6(0.635,2.75) 7(-0.635,2.75) 8(-1.905,2.75)
T114
  round 3.175 hole 2: 1(2.54,-3.5) 2(-2.54,-3.5) 3(-2.54,3.5) 4(2.54,3.5)
  round 0.01 hole 4: 5(0,0)
T146
  custom 0.6x0.6 smd: 1(-4.05,0) 2(4.05,0)

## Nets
VCC5: C63.1 C64.1 C65.1 C66.1 C67.1 C68.1 C87.1 C88.1 C90.1 C91.1 C113.2 C114.2 C121.1 C122.2 IC2.37 IC3.7 IC3.9 IC4.7 IC4.9 IC5.7 IC5.9 IC6.7 IC6.9 IC7.7 IC7.9 L10.2 R27.2 R28.2 R29.2 R34.2 R35.2 R37.1 R38.1 R41.2 R42.2 R43.2 R45.2 R46.2 R106.2 R107.2 R108.2 R109.2 R110.2 R111.2 R112.2 R113.2 R121.2 R122.2
VCC12: C109.1 C110.2 IC9.9 L3.2 R116.1
DRVCC: C5.1 D1.1 D2.1 IC1.10 IC1.26
ISEN1: C48.1 IC2.32 R76.2
ISEN1+: C42.1 IC2.33 R70.2
ISEN2: C50.1 IC2.26 R77.2
ISEN3: C52.1 IC2.35 R78.2
ISEN4: C54.1 IC2.29 R79.2
ISEN5: C56.1 IC2.23 R80.2
LGND: C1.2 C2.1 C3.2 C4.1 C5.2 C6.1 C7.2 C8.1 C9.2 C10.1 C11.2 C12.1 C13.2 C14.1 C15.2 C16.1 C21.2 C22.2 C23.2 C24.2 C25.2 C26.1 C28.2 C29.1 C30.2 C31.2 C32.2 C37.2 C39.2 C40.2 C41.2 C42.2 C43.2 C44.2 C45.2 C46.2 C49.2 C51.2 C53.2 C55.2 C57.2 C60.2 C61.2 C62.2 C63.2 C64.2 C65.2 C66.2 C67.2 C68.2 C72.2 C73.2 C74.2 C75.2 C76.2 C77.2 C78.2 C79.2 C80.2 C81.2 C82.2 C83.2 C84.2 C85.2 C87.2 C88.2 C90.2 C91.2 C96.2 C97.2 C99.2 C100.2 C102.2 C103.2 C105.2 C106.2 C108.1 C109.2 C110.1 C111.1 C114.1 C115.1 C116.1 C117.1 C118.1 C119.1 C120.1 C121.2 C122.1 C123.1 C124.1 C125.1 C126.1 C127.1 C128.1 C129.1 C130.1 C131.1 C132.1 C133.1 C134.1 C135.1 C136.1 C137.1 C138.1 C139.1 C140.1 C141.1 C142.1 C143.1 C144.1 C145.1 C146.1 C147.1 C148.1 C149.1 C150.1 C151.1 C152.1 C153.1 C154.1 C155.1 C156.1 C157.1 C158.1 C159.1 C160.1 C161.1 C162.1 C163.1 C164.1 CN1.2 E2.1 E2.2 E2.3 E2.4 E8.1 E8.2 E8.3 E8.4 IC1.4 IC1.5 IC1.9 IC1.15 IC1.16 IC1.25 IC1.49 IC2.49 IC3.5 IC3.11 IC4.5 IC4.11 IC5.5 IC5.11 IC6.5 IC6.11 IC7.5 IC7.11 IC9.11 Q2.1 Q2.2 Q2.3 Q4.1 Q4.2 Q4.3 Q6.1 Q6.2 Q6.3 Q8.1 Q8.2 Q8.3 Q10.1 Q10.2 Q10.3 Q11.1 Q11.2 Q11.3 Q12.1 Q12.2 Q12.3 Q13.1 Q13.2 Q13.3 Q15.1 Q15.2 Q15.3 Q17.1 Q17.2 Q17.3 Q20.1 Q20.2 Q20.3 Q21.1 Q21.2 Q21.3 R2.1 R4.1 R8.1 R11.1 R25.1 R26.1 R40.1 R44.2 R50.1 R51.1 R56.1 R59.1 R65.1 R66.1 R69.1 R114.1 R115.1 R117.1 R118.1 R119.1 R120.1 R123.1 R124.1 S1.1 S1.2 S1.3 S1.4 S1.5 S1.6 S1.7 S1.8
PG: C40.1 IC2.40 IC9.8 R67.2 R121.1
PWM1: C61.1 IC2.31 IC3.4
PWM2: C62.1 IC2.25 IC4.4
PWM3: C60.1 IC2.36 IC5.4
PWM4: C84.1 IC2.30 IC6.4
PWM5: C85.1 IC2.24 IC7.4
SIGN6423: Q2.4 R15.2
SIGN6441: Q1.4 R14.2
SIGN6492: C32.1 IC2.21 R29.1
SIGN6507: IC2.17 R57.2
SIGN6508: C33.1 R31.1
SIGN6511: C34.2 R33.2
SIGN6515: C37.1 IC2.13 R39.1
SIGN6516: IC2.20 R38.2 R65.2
SIGN6519: IC2.43 R37.2 R40.2
SIGN6523: IC2.10 R34.1 R50.2 R51.2
SIGN6527: C39.1 IC2.48 R45.1 R66.2
SIGN6529: IC2.46 R43.1
SIGN6530: IC2.44 R42.1
SIGN6532: C41.1 IC2.11 R46.1 R68.2
SIGN6534: C31.1 C38.1 IC2.18 R26.2
SIGN6540: IC2.41 R44.1 R67.1
SIGN6613: Q12.4 R90.2
SIGN6624: Q13.4 R93.2
SIGN6683: Q21.4 R100.2
SIGN6715: C43.1 IC2.27 R71.2
SIGN6717: C44.1 IC2.34 R72.2
SIGN6719: C45.1 IC2.28 R73.2
SIGN6721: C46.1 IC2.22 R74.2
SIGN6792: C111.2 IC9.7
SIGN6793: C112.1 IC9.2 L10.1
SIGN6794: C113.1 IC9.6 R114.2 R115.2 R122.1
SIGN6796: C108.2 IC9.3
SIGN6815: IC9.4 R118.2 R119.2
SIGN6816: IC2.42 R58.2
SIGN6820: IC2.45 R28.1
SIGN6828: C112.2 IC9.1
SIGN6838: IC9.5 R117.2
SIGN6946: IC1.37 R15.1
SIGN6947: IC1.42 R14.1
SIGN6948: C19.1 D1.2 R12.2
SIGN6954: C27.2 C28.1 IC1.47 R23.1 R24.1 R25.2
SIGN6957: IC1.6 R10.2
SIGN6960: C1.1 IC1.29 IC1.32 R2.2 R6.1
SIGN6989: C13.1 IC1.7
SIGN6992: IC1.2 R3.1 R4.2
SIGN7000: C11.1 R9.1
SIGN7001: R35.1 R56.2 R58.1 R59.2
SIGN7005: C15.1 IC1.45
SIGN7007: C9.1 IC1.46 R9.2
SIGN7059: C20.2 IC1.20 L2.2 Q3.1 Q3.2 Q3.3 Q4.5 Q4.6 Q4.7 Q4.8 R20.1
SIGN7062: IC1.21 R13.1
SIGN7068: IC1.19 R16.1
SIGN7069: C20.1 D2.2 R13.2
SIGN7071: IC1.24 R17.1
SIGN7073: Q3.4 R16.2
SIGN7074: Q4.4 R17.2
SIGN7078: IC1.40 R12.1
SIGN7084: C3.1 IC1.35 R1.2
SIGN7088: C7.1 IC1.3 IC1.14 R3.2 R7.2
SIGN7089: IC1.8 R7.1 R8.2
SIGN7090: C23.1 IC1.11 R22.2
SIGN7092: C17.1 IC1.48 R18.2 R21.1
SIGN7094: C18.2 IC1.13 R19.1 R20.2
SIGN7098: C36.2 IC2.14 R36.1
SIGN7099: C35.2 C36.1 IC2.15 R33.1 R36.2
SIGN7100: C33.2 C34.1 C35.1 IC2.16 R30.1
SIGN7102: R30.2 R49.2 R57.1
SIGN7103: R31.2 R32.1 R49.1
SIGN7104: C30.1 C38.2 IC2.19 R32.2 R48.2
SIGN7120: IC3.1 R85.1
SIGN7121: Q5.4 R85.2
SIGN7122: Q6.4 R86.2
SIGN7123: IC3.2 R82.1
SIGN7124: C69.1 R82.2
SIGN7125: Q11.4 R87.2
SIGN7126: IC3.6 R86.1 R87.1
SIGN7129: IC4.1 R88.1
SIGN7130: IC4.2 R83.1
SIGN7131: C70.1 R83.2
SIGN7132: Q7.4 R88.2
SIGN7135: IC4.6 R89.1 R90.1
SIGN7136: Q8.4 R89.2
SIGN7139: IC5.1 R91.1
SIGN7140: Q9.4 R91.2
SIGN7142: IC5.2 R84.1
SIGN7143: C71.1 R84.2
SIGN7144: IC5.6 R92.1 R93.1
SIGN7147: Q14.4 R101.2
SIGN7148: IC6.1 R101.1
SIGN7149: IC6.2 R94.1
SIGN7150: C93.1 R94.2
SIGN7151: Q15.4 R97.2
SIGN7152: Q20.4 R98.2
SIGN7153: IC6.6 R97.1 R98.1
SIGN7156: Q17.4 R99.2
SIGN7157: IC7.6 R99.1 R100.1
SIGN7158: Q16.4 R102.2
SIGN7159: IC7.1 R102.1
SIGN7160: IC7.2 R95.1
SIGN7161: C94.1 R95.2
SIGN7182: IC9.10 R116.2 R120.2
SIGN7185: IC2.8 R55.2
SIGN7189: IC2.6 R53.2
SIGN7191: IC2.5 R52.2
SIGN7192: IC2.7 R54.2
SIGN7193: IC2.4 R63.2
SIGN7195: IC2.3 R62.2
SIGN7198: IC2.1 R60.2
SIGN7199: IC2.2 R61.2
SIGN7201: IC2.9 R64.2
SIGN7202: CN1.1 R27.1 R64.1
SIGN7205: R5.1 R6.2
SIGN7206: R68.1 R69.2
SIGN7208: R10.1 R11.2
SIGN7217: IC2.12 R39.2
SIGN7218: IC2.47 R41.1
VID0: R55.1 R113.1 S1.16
VID1: R54.1 R112.1 S1.15
VID2: R53.1 R111.1 S1.14
VID3: R52.1 R110.1 S1.13
VID4: R63.1 R109.1 S1.12
VID5: R62.1 R108.1 S1.11
VID6: R61.1 R107.1 S1.10
VID7: R60.1 R106.1 S1.9
VP_1R2_VOUT: C48.2 C49.1 C50.2 C51.1 C52.2 C53.1 C54.2 C55.1 C56.2 C57.1 C115.2 C116.2 C117.2 C118.2 C119.2 C120.2 C123.2 C124.2 C125.2 C126.2 C127.2 C128.2 C129.2 C130.2 C131.2 C132.2 C133.2 C134.2 C135.2 C136.2 C137.2 C138.2 C139.2 C140.2 C141.2 C142.2 C143.2 C144.2 C145.2 C146.2 C147.2 C148.2 C149.2 C150.2 C151.2 C152.2 C153.2 C154.2 C155.2 C156.2 C157.2 C158.2 C159.2 C160.2 C161.2 C162.2 C163.2 C164.2 E7.1 E7.2 E7.3 E7.4 L4.2 L5.2 L6.2 L7.2 L8.2 R48.1 R70.1 R71.1 R72.1 R73.1 R74.1 R123.2 R124.2
VP_12V: C17.2 C18.1 C24.1 C25.1 C26.2 C27.1 C29.2 C72.1 C73.1 C74.1 C75.1 C76.1 C77.1 C78.1 C79.1 C80.1 C81.1 C82.1 C83.1 C96.1 C97.1 C99.1 C100.1 C102.1 C103.1 C105.1 C106.1 IC1.1 IC1.12 L1.2 L2.1 L3.1 Q5.5 Q5.6 Q5.7 Q5.8 Q7.5 Q7.6 Q7.7 Q7.8 Q9.5 Q9.6 Q9.7 Q9.8 Q14.5 Q14.6 Q14.7 Q14.8 Q16.5 Q16.6 Q16.7 Q16.8 R18.1 R19.2 R22.1 R23.2 R24.2
VP_50_VIN: C2.2 C4.2 C6.2 C8.2 C10.2 C12.2 C14.2 C16.2 C21.1 C22.1 E1.1 E1.2 E1.3 E1.4 Q1.5 Q1.6 Q1.7 Q1.8 Q3.5 Q3.6 Q3.7 Q3.8 R1.1 R5.2
N00200018: C19.2 IC1.41 L1.1 Q1.1 Q1.2 Q1.3 Q2.5 Q2.6 Q2.7 Q2.8 R21.2
N00400009: C69.2 IC3.10 L4.1 Q5.1 Q5.2 Q5.3 Q6.5 Q6.6 Q6.7 Q6.8 Q11.5 Q11.6 Q11.7 Q11.8 R76.1
N00400011: C70.2 IC4.10 L5.1 Q7.1 Q7.2 Q7.3 Q8.5 Q8.6 Q8.7 Q8.8 Q12.5 Q12.6 Q12.7 Q12.8 R77.1
N00400014: C71.2 IC5.10 L6.1 Q9.1 Q9.2 Q9.3 Q10.5 Q10.6 Q10.7 Q10.8 Q13.5 Q13.6 Q13.7 Q13.8 R78.1
N00400017: C93.2 IC6.10 L7.1 Q14.1 Q14.2 Q14.3 Q15.5 Q15.6 Q15.7 Q15.8 Q20.5 Q20.6 Q20.7 Q20.8 R79.1
N00400020: C94.2 IC7.10 L8.1 Q16.1 Q16.2 Q16.3 Q17.5 Q17.6 Q17.7 Q17.8 Q21.5 Q21.6 Q21.7 Q21.8 R80.1
N00400039: Q10.4 R92.2

Pads without a net: E1 5; E2 5; E7 5 6; E8 5 6; IC1 17 18 22 23 27 28 30 31 33 34 36 38 39 43 44; IC2 38 39; IC3 3 8; IC4 3 8; IC5 3 8; IC6 3 8; IC7 3 8; L1 3; L2 3

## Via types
v1: diameter 0.711, hole 0.4, TOP to BOTTOM, 162 vias
v2: diameter 1.397, hole 0.8, TOP to BOTTOM, 751 vias
v3: diameter 0.508, hole 0.3, TOP to BOTTOM, 24 vias

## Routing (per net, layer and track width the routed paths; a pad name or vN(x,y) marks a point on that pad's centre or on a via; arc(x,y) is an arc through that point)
VCC5: length 567.7
  TOP w0.35: 33.55,107.01 32.95,105.97 ; 32.95,105.97 31.37,104.39 31.37,85.74 R122.2 32.52,84.58 C113.2 ; 32.95,105.97 33.92,106.64 ; 32.95,105.97 34.11,106.45 ; 32.95,105.97 33.67,106.89 ; 32.95,105.97 33.8,106.76 ; 32.95,105.97 v2(33.91,106.93) ; 32.95,105.97 33.42,107.13 ; 34.02,84.59 C113.2 ; C113.2 34.54,84.07 36.58,84.07 R121.2 ; 50.39,98.33 50.72,98 IC2.37 ; 50.39,98.33 50.21,98.86 ; 50.39,98.33 49.93,98.66 ; 50.39,98.33 50.04,98.68 v1(50.04,98.81) ; 78.74,93.32 78.57,92.76 ; 78.74,93.32 78.91,92.76 ; 78.74,93.32 v1(78.74,92.71) ; 78.74,93.32 78.74,95.25 76.71,97.28 72.64,97.28 71.88,96.52 R28.2 R27.2
  TOP w0.635: 65.28,100.29 v1(65.28,99.82) 64.95,99.49 ; 65.28,100.29 65.32,99.83 ; 65.28,100.29 65.24,99.83 ; 65.28,100.29 65.28,100.33 66.17,101.22 R38.1 ; v1(20.7,127.89) 20.24,127.89 ; 20.24,127.89 20.07,127.89 C65.1 ; 20.24,127.89 20.7,127.93 ; 20.24,127.89 20.7,127.85 ; v1(72.52,127.89) 72.05,127.89 ; 72.05,127.89 71.88,127.89 C87.1 ; 72.05,127.89 72.51,127.85 ; 72.05,127.89 72.51,127.93 ; 72.54,129.19 72.19,129.49 ; 72.19,129.49 72.49,129.13 ; 72.19,129.49 v1(72.52,129.16) ; 72.19,129.49 71.63,130.05 C90.1 ; v2(11.68,102.36) 11.68,101.14 ; 11.68,101.14 11.32,102.24 ; 11.68,101.14 R106.2 R107.2 R108.2 R109.2 R110.2 R111.2 R112.2 R113.2 ; 11.68,101.14 11.64,102.24 ; 11.68,101.14 12.05,102.24 ; v2(33.91,106.93) 35.13,106.93 ; 35.13,106.93 34.03,106.57 ; 35.13,106.93 34.03,106.89 ; 35.13,106.93 C122.2 C121.1 35.31,103.67 C114.2 35.01,100.31 L10.2 ; 35.13,106.93 34.03,107.3 ; 46.63,129.19 46.28,129.49 ; 46.28,129.49 v1(46.61,129.16) ; 46.28,129.49 45.72,130.05 C66.1 ; 46.28,129.49 46.58,129.13 ; v1(20.7,129.16) 20.37,129.49 ; 20.37,129.49 19.81,130.05 C68.1 ; 20.37,129.49 20.67,129.13 ; 20.37,129.49 20.73,129.19 ; 46.14,127.89 45.97,127.89 C63.1 ; 46.14,127.89 46.61,127.93 ; 46.14,127.89 v1(46.61,127.89) ; 46.14,127.89 46.61,127.85 ; 43.39,96.01 R37.1 R42.2 R43.2 R41.2 R45.2 ; 43.39,96.01 42.93,96.05 ; 43.39,96.01 v1(42.93,96.01) ; 43.39,96.01 42.93,95.97 ; 60.74,84.08 60.71,84.54 ; 60.71,84.54 v1(60.71,84.07) ; 60.71,84.54 R34.2 ; 60.71,84.54 60.67,84.08 ; C91.1 123.44,130.05 124,129.49 ; 65.3,99.79 64.95,99.49 ; 64.95,99.49 64.01,98.55 R29.2 ; 64.95,99.49 65.25,99.85 ; 98.1,129.49 98.4,129.13 ; 98.1,129.49 97.54,130.05 C67.1 ; 98.1,129.49 v1(98.42,129.16) ; 98.1,129.49 98.45,129.19 ; R46.2 65.28,84.41 ; 65.28,84.41 65.24,83.95 ; 65.28,84.41 v1(65.28,83.95) ; 65.28,84.41 65.32,83.95 ; C88.1 123.7,127.89 123.87,127.89 ; 124.36,129.19 124,129.49 ; 124,129.49 v1(124.33,129.16) ; 124,129.49 124.3,129.13 ; 97.96,127.89 98.42,127.85 ; 97.96,127.89 v1(98.42,127.89) ; 97.96,127.89 98.42,127.93 ; 97.96,127.89 97.79,127.89 C64.1 ; 124.33,127.93 123.87,127.89 ; 123.87,127.89 v1(124.33,127.89) ; 123.87,127.89 124.33,127.85
  CONDUCTIVE2 w0.635: 124.52,127.93 124.33,128.69 ; 124.33,128.69 v1(124.33,129.16) ; 124.33,128.69 124.33,128.36 ; 124.33,128.69 124.15,127.93 ; 97.62,113.67 69.04,113.67 ; 97.62,113.67 98.38,113.48 ; 97.62,113.67 v1(98.42,113.67) 99.23,113.67 ; 97.62,113.67 98.38,113.85 ; 69.04,113.67 67.94,113.62 ; 69.04,113.67 v2(67.82,113.67) ; 69.04,113.67 67.94,114.03 ; 69.04,113.67 67.94,113.3 ; 124.33,127.09 124.33,115.82 122.17,113.67 99.23,113.67 ; 124.33,127.09 v1(124.33,127.89) 124.33,128.36 ; 124.33,127.09 124.15,127.84 ; 124.33,127.09 124.52,127.84 ; 34.27,107.05 33.91,108.15 ; 33.91,108.15 33.91,113.67 ; 33.91,108.15 33.55,107.05 ; 33.91,108.15 33.95,107.05 ; 33.91,108.15 v2(33.91,106.93) ; 33.91,113.67 42.72,113.67 ; 33.91,113.67 21.5,113.67 ; 98.47,113.48 99.23,113.67 ; 99.23,113.67 98.47,113.85 ; 42.72,113.67 43.82,113.71 ; 42.72,113.67 43.82,114.03 ; 42.72,113.67 43.82,113.3 ; 42.72,113.67 v2(43.94,113.67) ; 21.5,113.67 v1(20.7,113.67) ; 21.5,113.67 20.75,113.48 ; 21.5,113.67 20.75,113.85 ; 124.33,128.36 124.52,129.11 ; 124.33,128.36 124.15,129.11
  CONDUCTIVE3 w0.635: 98.42,114.47 v1(98.42,113.67) ; 98.42,114.47 98.24,113.71 ; 98.42,114.47 98.61,113.71 ; 98.42,114.47 98.42,127.09 ; 46.04,127.32 v1(46.61,127.89) 46.61,128.36 ; 46.04,127.32 46.45,127.99 ; 46.04,127.32 45.09,126.36 45.09,114.81 44.8,114.53 ; 46.04,127.32 46.71,127.73 ; 20.7,128.69 20.52,127.93 ; 20.7,128.69 20.89,127.93 ; 20.7,128.69 v1(20.7,129.16) ; 20.7,128.69 20.7,128.36 ; 46.79,127.93 46.61,128.69 ; 46.61,128.69 v1(46.61,129.16) ; 46.61,128.69 46.61,128.36 ; 46.61,128.69 46.42,127.93 ; 65.12,99.92 64.71,99.26 ; 64.71,99.26 64.26,98.81 52.7,98.81 50.67,96.77 43.69,96.77 43.49,96.58 ; 64.71,99.26 65.38,99.66 ; 64.71,99.26 v1(65.28,99.82) ; 44.8,114.53 44.06,113.72 ; 44.8,114.53 44.28,113.49 ; 44.8,114.53 v2(43.94,113.67) ; 44.8,114.53 43.77,114.01 ; 72.52,127.09 v1(72.52,127.89) 72.52,128.36 ; 72.52,127.09 72.52,118.36 68.68,114.53 ; 72.52,127.09 72.33,127.84 ; 72.52,127.09 72.7,127.84 ; 20.89,113.71 20.7,114.47 ; 20.7,114.47 20.52,113.71 ; 20.7,114.47 v1(20.7,113.67) ; 20.7,114.47 20.7,127.09 ; 20.52,127.84 20.7,127.09 ; 20.7,127.09 20.89,127.84 ; 20.7,127.09 v1(20.7,127.89) 20.7,128.36 ; 20.7,128.36 20.89,129.11 ; 20.7,128.36 20.52,129.11 ; 43.09,95.91 43.49,96.58 ; 43.49,96.58 v1(42.93,96.01) ; 43.49,96.58 42.83,96.17 ; 72.52,128.69 v1(72.52,129.16) ; 72.52,128.69 72.7,127.93 ; 72.52,128.69 72.33,127.93 ; 72.52,128.69 72.52,128.36 ; 98.42,128.69 v1(98.42,129.16) ; 98.42,128.69 98.42,128.36 ; 98.42,128.69 98.61,127.93 ; 98.42,128.69 98.24,127.93 ; 72.52,128.36 72.7,129.11 ; 72.52,128.36 72.33,129.11 ; 98.42,128.36 v1(98.42,127.89) 98.42,127.09 ; 98.42,128.36 98.61,129.11 ; 98.42,128.36 98.24,129.11 ; 46.42,129.11 46.61,128.36 ; 46.61,128.36 46.79,129.11 ; 68.68,114.53 67.93,113.72 ; 68.68,114.53 v2(67.82,113.67) ; 68.68,114.53 67.65,114.01 ; 68.68,114.53 68.16,113.49 ; 98.42,127.09 98.61,127.84 ; 98.42,127.09 98.24,127.84
  CONDUCTIVE4 w0.635: 66.6,113.67 67.7,113.71 ; 66.6,113.67 45.16,113.67 ; 66.6,113.67 67.7,114.03 ; 66.6,113.67 67.7,113.3 ; 66.6,113.67 v2(67.82,113.67) ; 44.06,113.3 45.16,113.67 ; 45.16,113.67 44.06,114.03 ; 45.16,113.67 v2(43.94,113.67) ; 45.16,113.67 44.06,113.62
  BOTTOM w0.3: v1(98.42,127.89) 97.79,127.89 ; 97.79,127.89 98.36,127.69 ; 97.79,127.89 98.36,128.08 ; 97.79,127.89 96.72,127.89 96.59,128.02 IC4.9 ; 97.79,127.89 98.36,127.93 ; 46.54,128.08 45.98,127.89 ; 45.98,127.89 v1(46.61,127.89) ; 45.98,127.89 46.54,127.93 ; 45.98,127.89 44.91,127.89 44.77,128.02 IC3.9 ; 45.98,127.89 46.54,127.69 ; 123.7,127.89 124.27,127.93 ; 123.7,127.89 124.27,128.08 ; 123.7,127.89 v1(124.33,127.89) ; 123.7,127.89 122.63,127.89 122.49,128.02 IC7.9 ; 123.7,127.89 124.27,127.69 ; IC5.9 18.86,128.02 19,127.89 20.07,127.89 ; 98.36,128.96 97.79,129.16 ; 97.79,129.16 98.36,129.35 ; 97.79,129.16 96.72,129.16 96.59,129.02 IC4.7 ; 97.79,129.16 98.36,129.2 ; 97.79,129.16 v1(98.42,129.16) ; 20.63,127.69 20.07,127.89 ; 20.07,127.89 20.63,127.93 ; 20.07,127.89 v1(20.7,127.89) ; 20.07,127.89 20.63,128.08 ; 20.07,129.16 20.63,129.2 ; 20.07,129.16 19,129.16 18.86,129.02 IC5.7 ; 20.07,129.16 20.63,128.96 ; 20.07,129.16 20.63,129.35 ; 20.07,129.16 v1(20.7,129.16) ; IC7.7 122.49,129.02 122.63,129.16 123.7,129.16 ; 124.27,129.35 123.7,129.16 ; 123.7,129.16 v1(124.33,129.16) ; 123.7,129.16 124.27,129.2 ; 123.7,129.16 124.27,128.96 ; 46.54,129.35 45.98,129.16 ; 45.98,129.16 46.54,129.2 ; 45.98,129.16 v1(46.61,129.16) ; 45.98,129.16 46.54,128.96 ; 45.98,129.16 44.91,129.16 44.77,129.02 IC3.7 ; 71.88,129.16 72.45,129.2 ; 71.88,129.16 72.45,128.96 ; 71.88,129.16 72.45,129.35 ; 71.88,129.16 v1(72.52,129.16) ; 71.88,129.16 70.81,129.16 70.68,129.02 IC6.7 ; IC6.9 70.68,128.02 70.81,127.89 71.88,127.89 ; 72.45,128.08 71.88,127.89 ; 71.88,127.89 v1(72.52,127.89) ; 71.88,127.89 72.45,127.69 ; 71.88,127.89 72.45,127.93
  BOTTOM w0.635: 42.6,96.34 41.91,97.03 41.91,98.3 42.67,99.06 R35.2 43.94,100.46 ; 42.6,96.34 42.9,95.99 ; 42.6,96.34 42.95,96.04 ; 42.6,96.34 v1(42.93,96.01) 42.93,95.55 ; 65.3,83.92 64.95,83.62 ; 64.95,83.62 64.39,83.06 61.72,83.06 61.03,83.75 ; 64.95,83.62 65.25,83.97 ; 64.95,83.62 v1(65.28,83.95) 65.61,83.62 ; 43.94,100.46 48.39,100.46 49.71,99.13 ; 43.94,100.46 43.94,100.58 37.59,106.93 35.13,106.93 ; 42.93,95.55 42.93,87.63 47.5,83.06 59.69,83.06 60.38,83.75 ; 42.93,95.55 42.89,96.01 ; 42.93,95.55 42.96,96.01 ; 12.02,102.19 12.55,103.22 ; 12.55,103.22 v2(11.68,102.36) ; 12.55,103.22 11.8,102.41 ; 12.55,103.22 11.51,102.7 ; 12.55,103.22 16.26,106.93 32.69,106.93 ; 65.61,83.62 65.31,83.97 ; 65.61,83.62 65.25,83.92 ; 65.61,83.62 66.17,83.06 69.85,83.06 78.74,91.95 78.74,92.25 ; 50.06,98.84 49.71,99.13 ; 49.71,99.13 50.01,98.78 ; 49.71,99.13 v1(50.04,98.81) ; 33.79,106.57 32.69,106.93 ; 32.69,106.93 v2(33.91,106.93) 35.13,106.93 ; 32.69,106.93 33.79,106.98 ; 32.69,106.93 33.79,107.3 ; 61.03,83.75 v1(60.71,84.07) 60.38,83.75 ; 61.03,83.75 60.68,84.04 ; 61.03,83.75 60.74,84.1 ; 78.74,92.25 78.78,92.71 ; 78.74,92.25 v1(78.74,92.71) ; 78.74,92.25 78.7,92.71 ; 60.38,83.75 60.73,84.04 ; 60.38,83.75 60.68,84.1 ; 35.13,106.93 34.03,106.57 ; 35.13,106.93 34.03,106.89 ; 35.13,106.93 34.03,107.3
